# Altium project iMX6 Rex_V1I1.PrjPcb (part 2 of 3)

## Sheet [08] - CPU - SPI, I2C, SD, MMC.SchDoc
size A2; DocumentNumber: 8; SheetNumber: 8; SheetTotal: 20
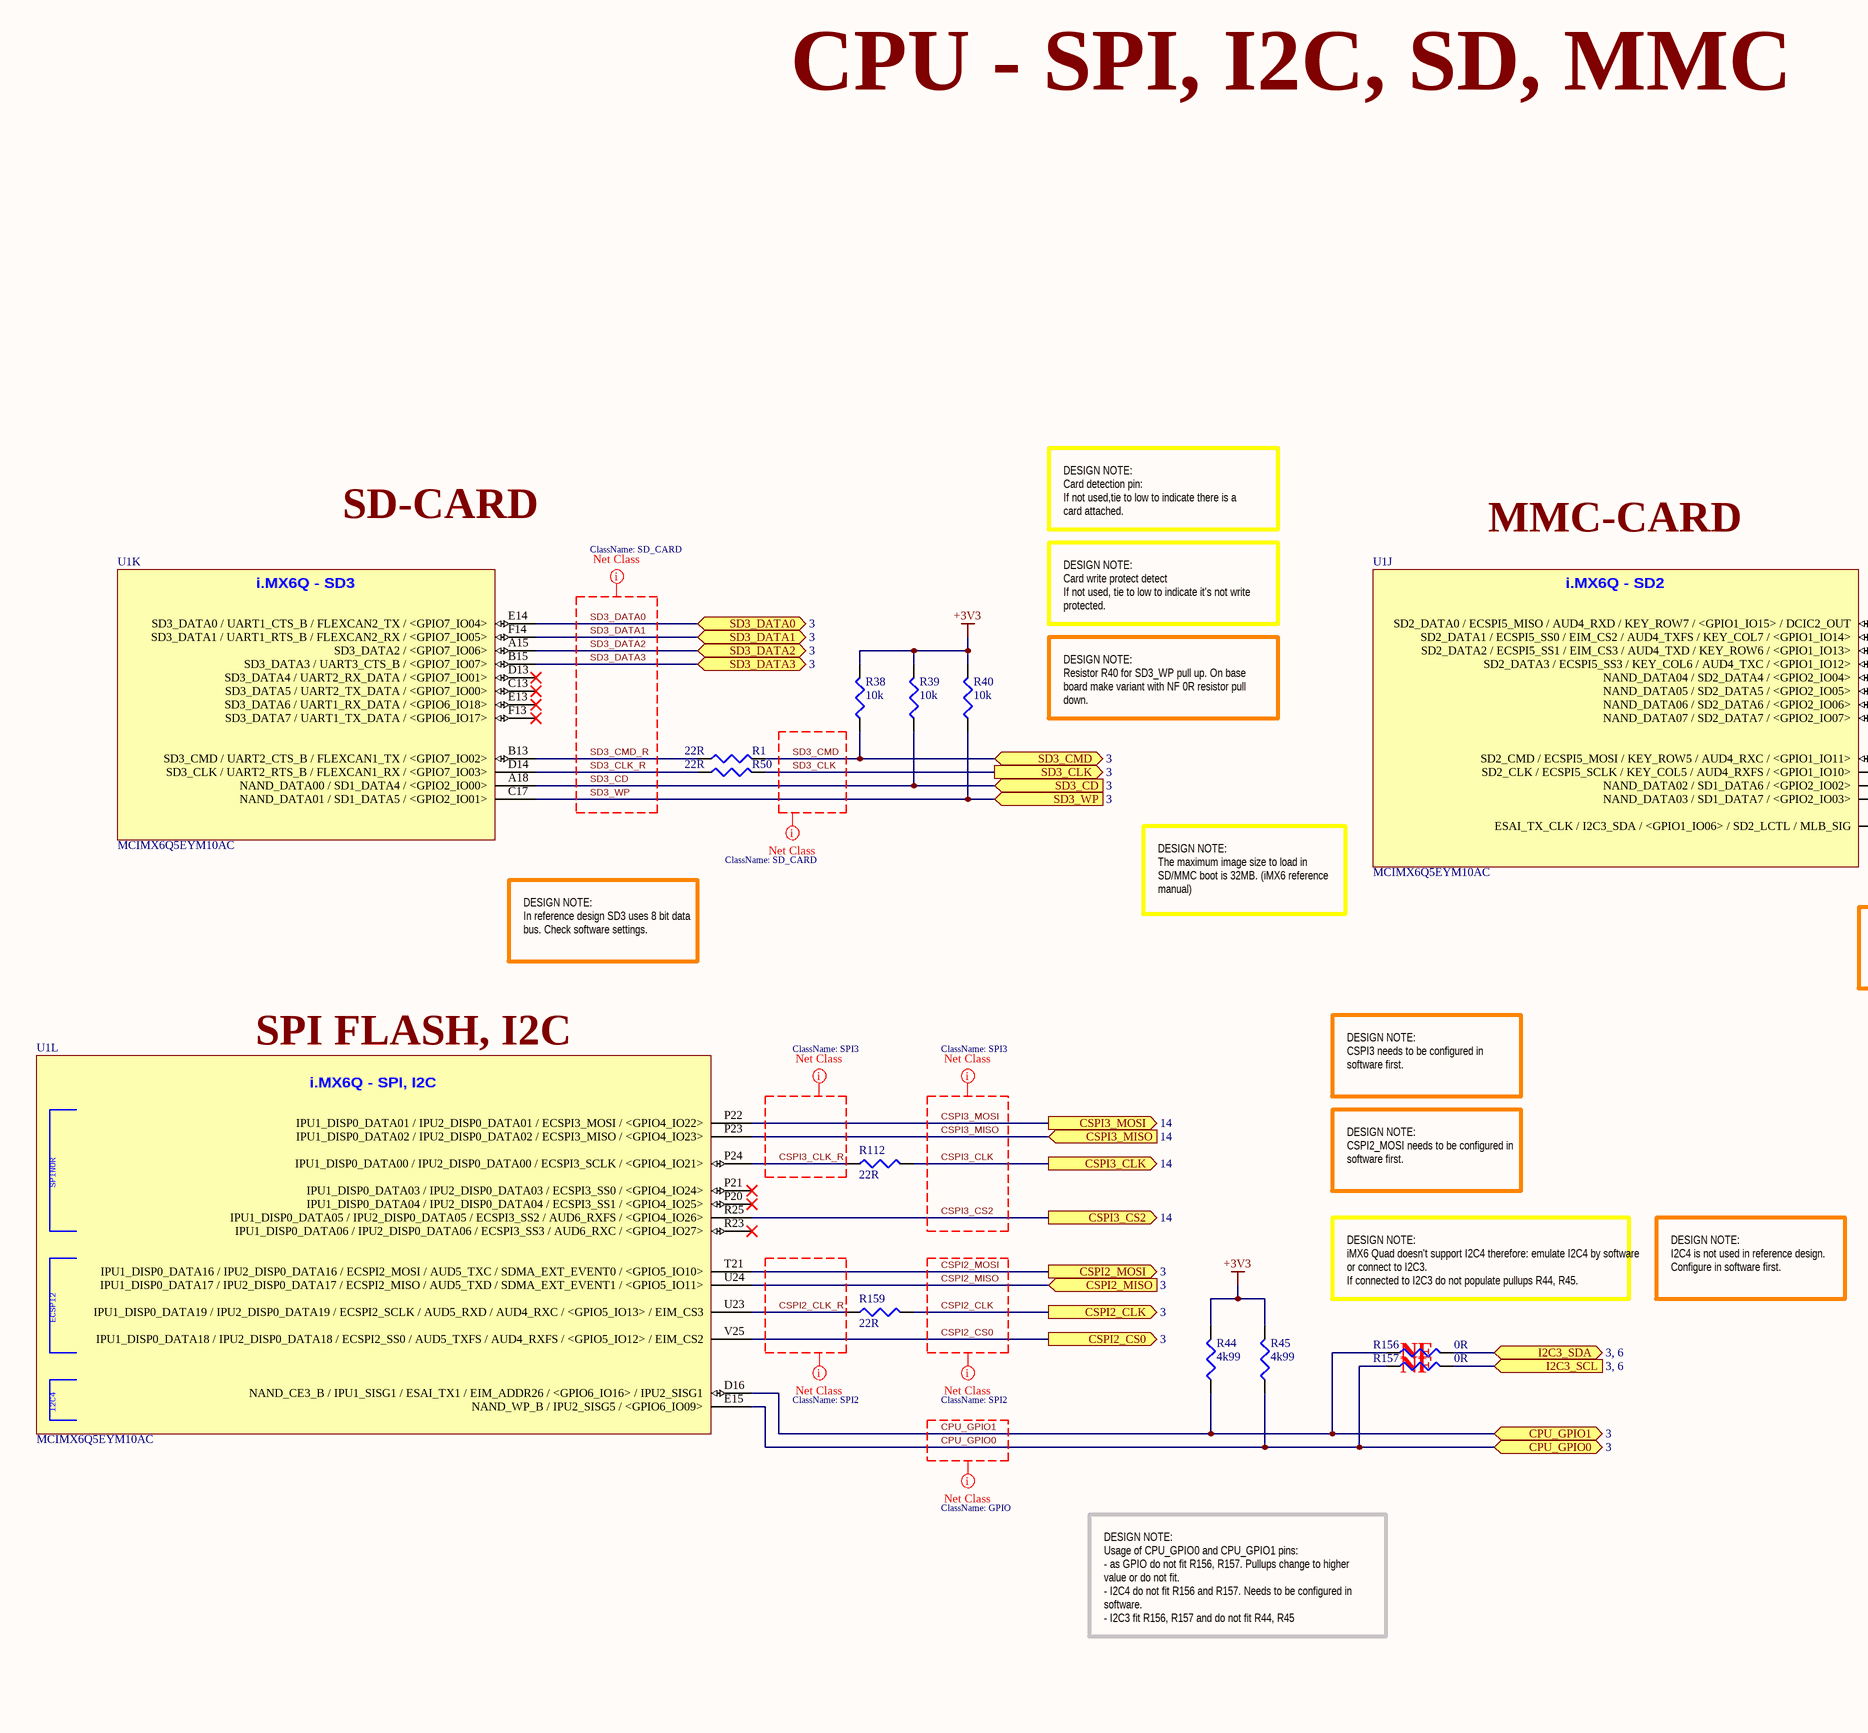
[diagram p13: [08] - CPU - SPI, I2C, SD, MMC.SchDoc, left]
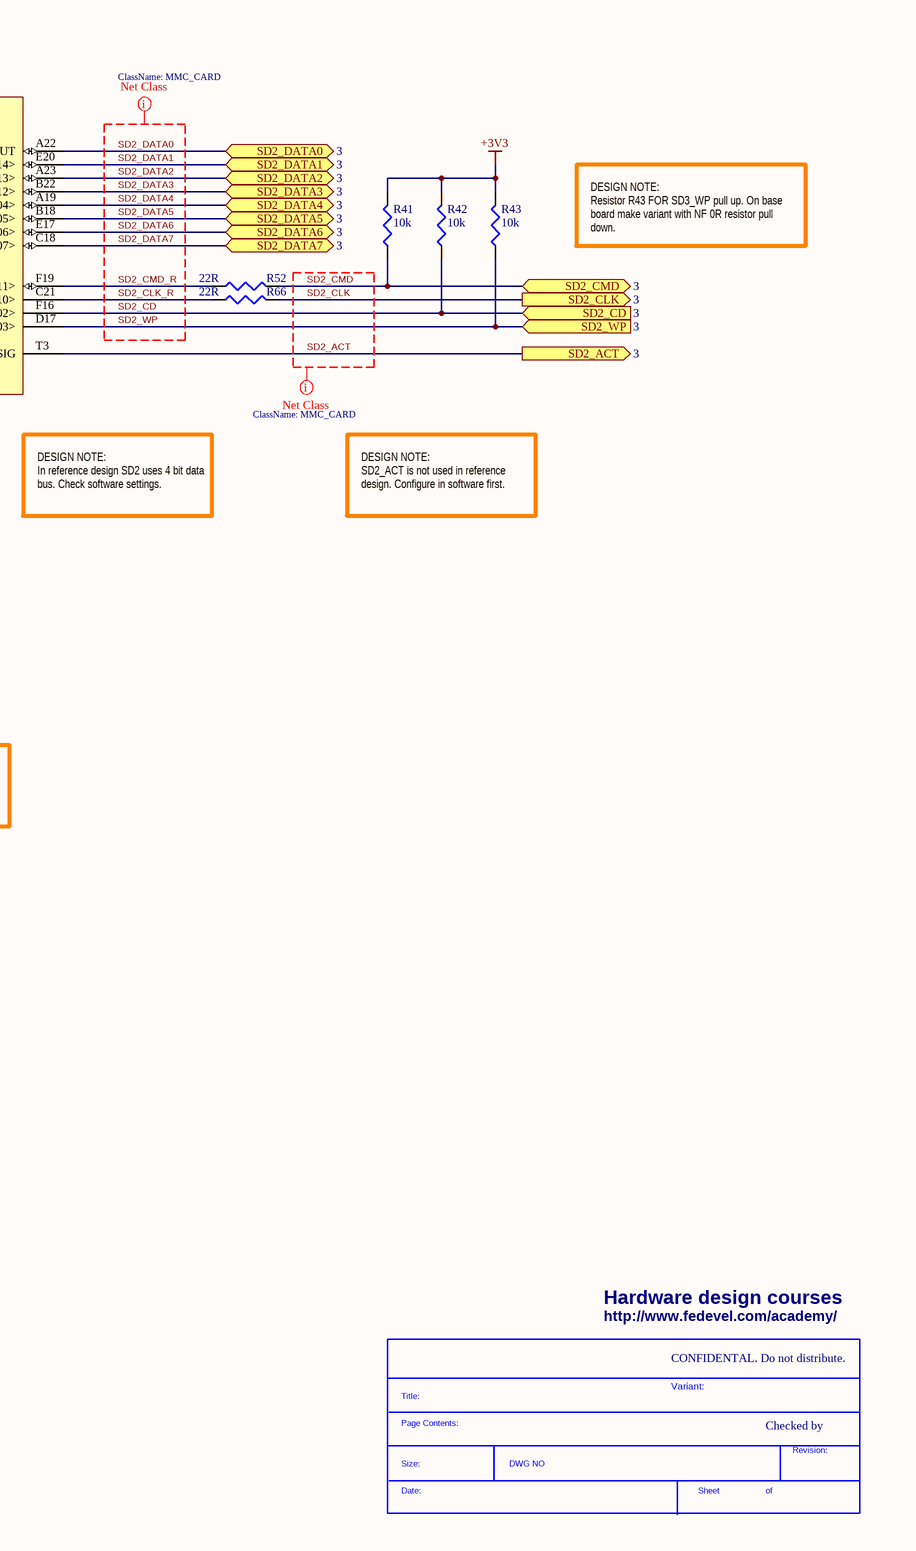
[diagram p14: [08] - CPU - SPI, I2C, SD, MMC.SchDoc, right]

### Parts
(Parts that share a designator on the sheet are numbered #1, #2 ... from top to bottom, then left to right.)
*#10  SDTitleBlock  (value not drawn)  (graphical)
R1  22R  [R0402]
R38  10k  [R0402]
R39  10k  [R0402]
R40  10k  [R0402]
R41  10k  [R0402]
R42  10k  [R0402]
R43  10k  [R0402]
R44  4k99  [R0402]
R45  4k99  [R0402]
R50  22R  [R0402]
R52  22R  [R0402]
R66  22R  [R0402]
R112  22R  [R0402]
R156  0R  [R0402]
R157  0R  [R0402]
R159  22R  [R0402]
U1  MCIMX6Q5EYM10AC  [PBGA624]  (parts J,K,L of 15)

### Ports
CPU_GPIO0 (bidir, see 3), CPU_GPIO1 (bidir, see 3), CSPI2_CLK (out, see 3), CSPI2_CS0 (out, see 3), CSPI2_MISO (in, see 3), CSPI2_MOSI (out, see 3), CSPI3_CLK (out, see 14), CSPI3_CS2 (out, see 14), CSPI3_MISO (in, see 14), CSPI3_MOSI (out, see 14), I2C3_SCL (see 3, 6), I2C3_SDA (bidir, see 3, 6), SD2_ACT (out, see 3), SD2_CD (in, see 3), SD2_CLK (out, see 3), SD2_CMD (bidir, see 3), SD2_DATA0 (bidir, see 3), SD2_DATA1 (bidir, see 3), SD2_DATA2 (bidir, see 3), SD2_DATA3 (bidir, see 3), SD2_DATA4 (bidir, see 3), SD2_DATA5 (bidir, see 3), SD2_DATA6 (bidir, see 3), SD2_DATA7 (bidir, see 3), SD2_WP (in, see 3), SD3_CD (in, see 3), SD3_CLK (out, see 3), SD3_CMD (bidir, see 3), SD3_DATA0 (bidir, see 3), SD3_DATA1 (bidir, see 3), SD3_DATA2 (bidir, see 3), SD3_DATA3 (bidir, see 3), SD3_WP (in, see 3)

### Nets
+3V3: R38.2 R39.2 R40.2 R41.2 R42.2 R43.2 R44.2 R45.2
CPU_GPIO0: R45.1 R157.1 U1.E15(NAND_WP_B_/_IPU2_SISG5_/_<GPIO6_IO09>) ; port CPU_GPIO0
CPU_GPIO1: R44.1 R156.1 U1.D16(NAND_CE3_B_/_IPU1_SISG1_/_ESAI_TX1_/_EIM_ADDR26_/_<GPIO6_IO16>_/_IPU2_SISG1) ; port CPU_GPIO1
CSPI2_CLK: R159.2 ; port CSPI2_CLK
CSPI2_CLK_R: R159.1 U1.U23(IPU1_DISP0_DATA19_/_IPU2_DISP0_DATA19_/_ECSPI2_SCLK_/_AUD5_RXD_/_AUD4_RXC_/_<GPIO5_IO13>_/_EIM_CS3)
CSPI2_CS0: U1.V25(IPU1_DISP0_DATA18_/_IPU2_DISP0_DATA18_/_ECSPI2_SS0_/_AUD5_TXFS_/_AUD4_RXFS_/_<GPIO5_IO12>_/_EIM_CS2) ; port CSPI2_CS0
CSPI2_MISO: U1.U24(IPU1_DISP0_DATA17_/_IPU2_DISP0_DATA17_/_ECSPI2_MISO_/_AUD5_TXD_/_SDMA_EXT_EVENT1_/_<GPIO5_IO11>) ; port CSPI2_MISO
CSPI2_MOSI: U1.T21(IPU1_DISP0_DATA16_/_IPU2_DISP0_DATA16_/_ECSPI2_MOSI_/_AUD5_TXC_/_SDMA_EXT_EVENT0_/_<GPIO5_IO10>) ; port CSPI2_MOSI
CSPI3_CLK: R112.2 ; port CSPI3_CLK
CSPI3_CLK_R: R112.1 U1.P24(IPU1_DISP0_DATA00_/_IPU2_DISP0_DATA00_/_ECSPI3_SCLK_/_<GPIO4_IO21>)
CSPI3_CS2: U1.R25(IPU1_DISP0_DATA05_/_IPU2_DISP0_DATA05_/_ECSPI3_SS2_/_AUD6_RXFS_/_<GPIO4_IO26>) ; port CSPI3_CS2
CSPI3_MISO: U1.P23(IPU1_DISP0_DATA02_/_IPU2_DISP0_DATA02_/_ECSPI3_MISO_/_<GPIO4_IO23>) ; port CSPI3_MISO
CSPI3_MOSI: U1.P22(IPU1_DISP0_DATA01_/_IPU2_DISP0_DATA01_/_ECSPI3_MOSI_/_<GPIO4_IO22>) ; port CSPI3_MOSI
I2C3_SCL: R157.2 ; port I2C3_SCL
I2C3_SDA: R156.2 ; port I2C3_SDA
SD2_ACT: U1.T3(ESAI_TX_CLK_/_I2C3_SDA_/_<GPIO1_IO06>_/_SD2_LCTL_/_MLB_SIG) ; port SD2_ACT
SD2_CD: R42.1 U1.F16(NAND_DATA02_/_SD1_DATA6_/_<GPIO2_IO02>) ; port SD2_CD
SD2_CLK: R66.2 ; port SD2_CLK
SD2_CLK_R: R66.1 U1.C21(SD2_CLK_/_ECSPI5_SCLK_/_KEY_COL5_/_AUD4_RXFS_/_<GPIO1_IO10>)
SD2_CMD: R41.1 R52.2 ; port SD2_CMD
SD2_CMD_R: R52.1 U1.F19(SD2_CMD_/_ECSPI5_MOSI_/_KEY_ROW5_/_AUD4_RXC_/_<GPIO1_IO11>)
SD2_DATA0: U1.A22(SD2_DATA0_/_ECSPI5_MISO_/_AUD4_RXD_/_KEY_ROW7_/_<GPIO1_IO15>_/_DCIC2_OUT) ; port SD2_DATA0
SD2_DATA1: U1.E20(SD2_DATA1_/_ECSPI5_SS0_/_EIM_CS2_/_AUD4_TXFS_/_KEY_COL7_/_<GPIO1_IO14>) ; port SD2_DATA1
SD2_DATA2: U1.A23(SD2_DATA2_/_ECSPI5_SS1_/_EIM_CS3_/_AUD4_TXD_/_KEY_ROW6_/_<GPIO1_IO13>) ; port SD2_DATA2
SD2_DATA3: U1.B22(SD2_DATA3_/_ECSPI5_SS3_/_KEY_COL6_/_AUD4_TXC_/_<GPIO1_IO12>) ; port SD2_DATA3
SD2_DATA4: U1.A19(NAND_DATA04_/_SD2_DATA4_/_<GPIO2_IO04>) ; port SD2_DATA4
SD2_DATA5: U1.B18(NAND_DATA05_/_SD2_DATA5_/_<GPIO2_IO05>) ; port SD2_DATA5
SD2_DATA6: U1.E17(NAND_DATA06_/_SD2_DATA6_/_<GPIO2_IO06>) ; port SD2_DATA6
SD2_DATA7: U1.C18(NAND_DATA07_/_SD2_DATA7_/_<GPIO2_IO07>) ; port SD2_DATA7
SD2_WP: R43.1 U1.D17(NAND_DATA03_/_SD1_DATA7_/_<GPIO2_IO03>) ; port SD2_WP
SD3_CD: R39.1 U1.A18(NAND_DATA00_/_SD1_DATA4_/_<GPIO2_IO00>) ; port SD3_CD
SD3_CLK: R50.2 ; port SD3_CLK
SD3_CLK_R: R50.1 U1.D14(SD3_CLK_/_UART2_RTS_B_/_FLEXCAN1_RX_/_<GPIO7_IO03>)
SD3_CMD: R1.2 R38.1 ; port SD3_CMD
SD3_CMD_R: R1.1 U1.B13(SD3_CMD_/_UART2_CTS_B_/_FLEXCAN1_TX_/_<GPIO7_IO02>)
SD3_DATA0: U1.E14(SD3_DATA0_/_UART1_CTS_B_/_FLEXCAN2_TX_/_<GPIO7_IO04>) ; port SD3_DATA0
SD3_DATA1: U1.F14(SD3_DATA1_/_UART1_RTS_B_/_FLEXCAN2_RX_/_<GPIO7_IO05>) ; port SD3_DATA1
SD3_DATA2: U1.A15(SD3_DATA2_/_<GPIO7_IO06>) ; port SD3_DATA2
SD3_DATA3: U1.B15(SD3_DATA3_/_UART3_CTS_B_/_<GPIO7_IO07>) ; port SD3_DATA3
SD3_WP: R40.1 U1.C17(NAND_DATA01_/_SD1_DATA5_/_<GPIO2_IO01>) ; port SD3_WP

Not connected (* = marked no-connect by the designer): U1 C13(SD3_DATA5_/_UART2_TX_DATA_/_<GPIO7_IO00>)* D13(SD3_DATA4_/_UART2_RX_DATA_/_<GPIO7_IO01>)* E13(SD3_DATA6_/_UART1_RX_DATA_/_<GPIO6_IO18>)* F13(SD3_DATA7_/_UART1_TX_DATA_/_<GPIO6_IO17>)* P20(IPU1_DISP0_DATA04_/_IPU2_DISP0_DATA04_/_ECSPI3_SS1_/_<GPIO4_IO25>)* P21(IPU1_DISP0_DATA03_/_IPU2_DISP0_DATA03_/_ECSPI3_SS0_/_<GPIO4_IO24>)* R23(IPU1_DISP0_DATA06_/_IPU2_DISP0_DATA06_/_ECSPI3_SS3_/_AUD6_RXC_/_<GPIO4_IO27>)*

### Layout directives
net class SPI3: CSPI3_CLK, CSPI3_CLK_R, CSPI3_CS2, CSPI3_MISO, CSPI3_MOSI
net class SPI2: CSPI2_CLK, CSPI2_CLK_R, CSPI2_CS0, CSPI2_MISO, CSPI2_MOSI
net class GPIO: CPU_GPIO0, CPU_GPIO1
net class SD_CARD: SD3_CD, SD3_CLK, SD3_CLK_R, SD3_CMD, SD3_CMD_R, SD3_DATA0, SD3_DATA1, SD3_DATA2, SD3_DATA3, SD3_WP
net class MMC_CARD: SD2_ACT, SD2_CD, SD2_CLK, SD2_CLK_R, SD2_CMD, SD2_CMD_R, SD2_DATA0, SD2_DATA1, SD2_DATA2, SD2_DATA3, SD2_DATA4, SD2_DATA5, SD2_DATA6, SD2_DATA7, SD2_WP

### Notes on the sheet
- CPU - SPI, I2C, SD, MMC
- SD-CARD
- DESIGN NOTE:
  Card detection pin:
  If not used,tie to low to indicate there is a card attached.
- MMC-CARD
- DESIGN NOTE:
  Card write protect detect
  If not used, tie to low to indicate it's not write protected.
- DESIGN NOTE:
  Resistor R40 for SD3_WP pull up. On base board make variant with NF 0R resistor pull down.
- DESIGN NOTE:
  Resistor R43 FOR SD3_WP pull up. On base board make variant with NF 0R resistor pull down.
- DESIGN NOTE:
  The maximum image size to load in SD/MMC boot is 32MB. (iMX6 reference manual)
- DESIGN NOTE:
  In reference design SD3 uses 8 bit data bus. Check software settings.
- DESIGN NOTE:
  In reference design SD2 uses 4 bit data bus. Check software settings.
- DESIGN NOTE:
  SD2_ACT is not used in reference design. Configure in software first.
- SPI FLASH, I2C
- DESIGN NOTE:
  CSPI3 needs to be configured in software first.
- DESIGN NOTE:
  CSPI2_MOSI needs to be configured in software first.
- DESIGN NOTE:
  iMX6 Quad doesn't support I2C4 therefore: emulate I2C4 by software or connect to I2C3.
  If connected to I2C3 do not populate pullups R44, R45.
- DESIGN NOTE:
  I2C4 is not used in reference design. Configure in software first.
- NF
- DESIGN NOTE:
  Usage of CPU_GPIO0 and CPU_GPIO1 pins:
  - as GPIO do not fit R156, R157. Pullups change to higher value or do not fit.
  - I2C4 do not fit R156 and R157. Needs to be configured in software.
  - I2C3 fit R156, R157 and do not fit R44, R45
- Hardware design courses
- http://www.fedevel.com/academy/
- CONFIDENTAL. Do not distribute.
- Variant:
- Checked by

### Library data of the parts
R1 R50 R52 R66 R112 R159 = RC0402FR-0722RL: RES 22.0 OHM 1/16W 1% 0402 SMD; Manufacturer: Yageo; Resistance (Ohms): 22; Power (Watts): 0.063W, 1/16W; .Checked PCB: used; Temperature Coefficient: ±100ppm/°C
R38-R43 = RC0402FR-0710KL: RES 10.0K OHM 1/16W 1% 0402 SMD; Manufacturer: Yageo; Power (Watts): 0.063W, 1/16W; .Checked PCB: used; Temperature Coefficient: ±100ppm/°C
R44 R45 = RMCF0402FT4K99: RES TF 4.99K OHM 1% 1/16W 0402; Manufacturer: Stackpole Electronics Inc; Power (Watts): 0.063W, 1/16W; .Checked PCB: used; Temperature Coefficient: ±100ppm/°C
R156 R157 = RC0402JR-070RL: RES 0.0 OHM 1/16W 0402 SMD; Manufacturer: Yageo; Resistance (Ohms): 0.0; Power (Watts): 0.063W, 1/16W; Tolerance: Jumper; .Checked PCB: used
U1 = MCIMX6Q5EYM10AC: IC MCU 32BIT ARM QUAD 624FCBGA; Manufacturer: Freescale Semiconductor; Core Processor: ARM® Cortex™-A9; Core Size: 32-Bit Quad-Core; Speed: 1.0GHz; Connectivity: CAN, EBI/EMI, ESAI, Ethernet, GPMI, I2C, MMC/SD, PCI, SATA, SPI, UART, USB, USB OTG; Peripherals: DMA, HDMI, I2S/SSI/AC97, MIPI CSI, MIMI DSI, MIPI HIS, PWM, WDT; Number of I /O: 224; Program Memory Type: External Program Memory; RAM Size: 256K x 8; Voltage - Supply (Vcc/Vdd): 0.925 V ~ 1.5 V; Oscillator Type: Internal; .Creator: MM; .Checked PCB: MM, checked by RF

## Sheet [03] - CONNECTORS.SchDoc
size A2; DocumentNumber: 3; SheetNumber: 3; SheetTotal: 20
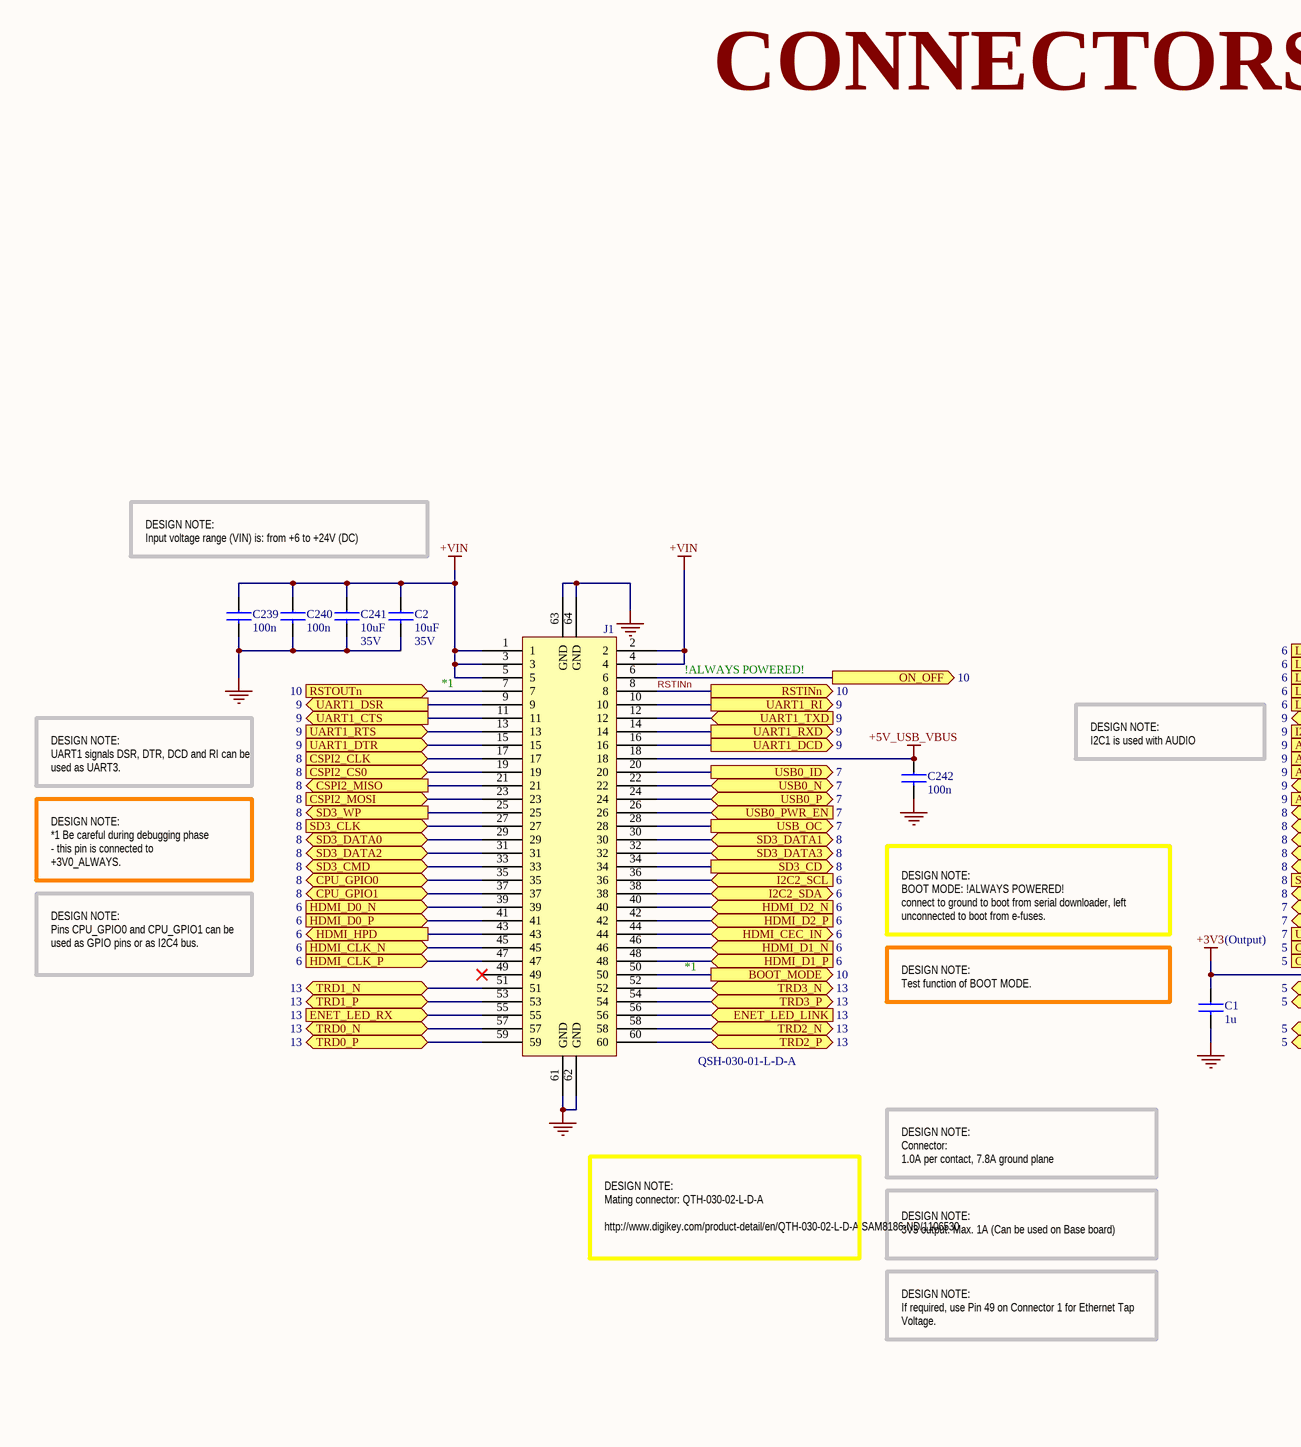
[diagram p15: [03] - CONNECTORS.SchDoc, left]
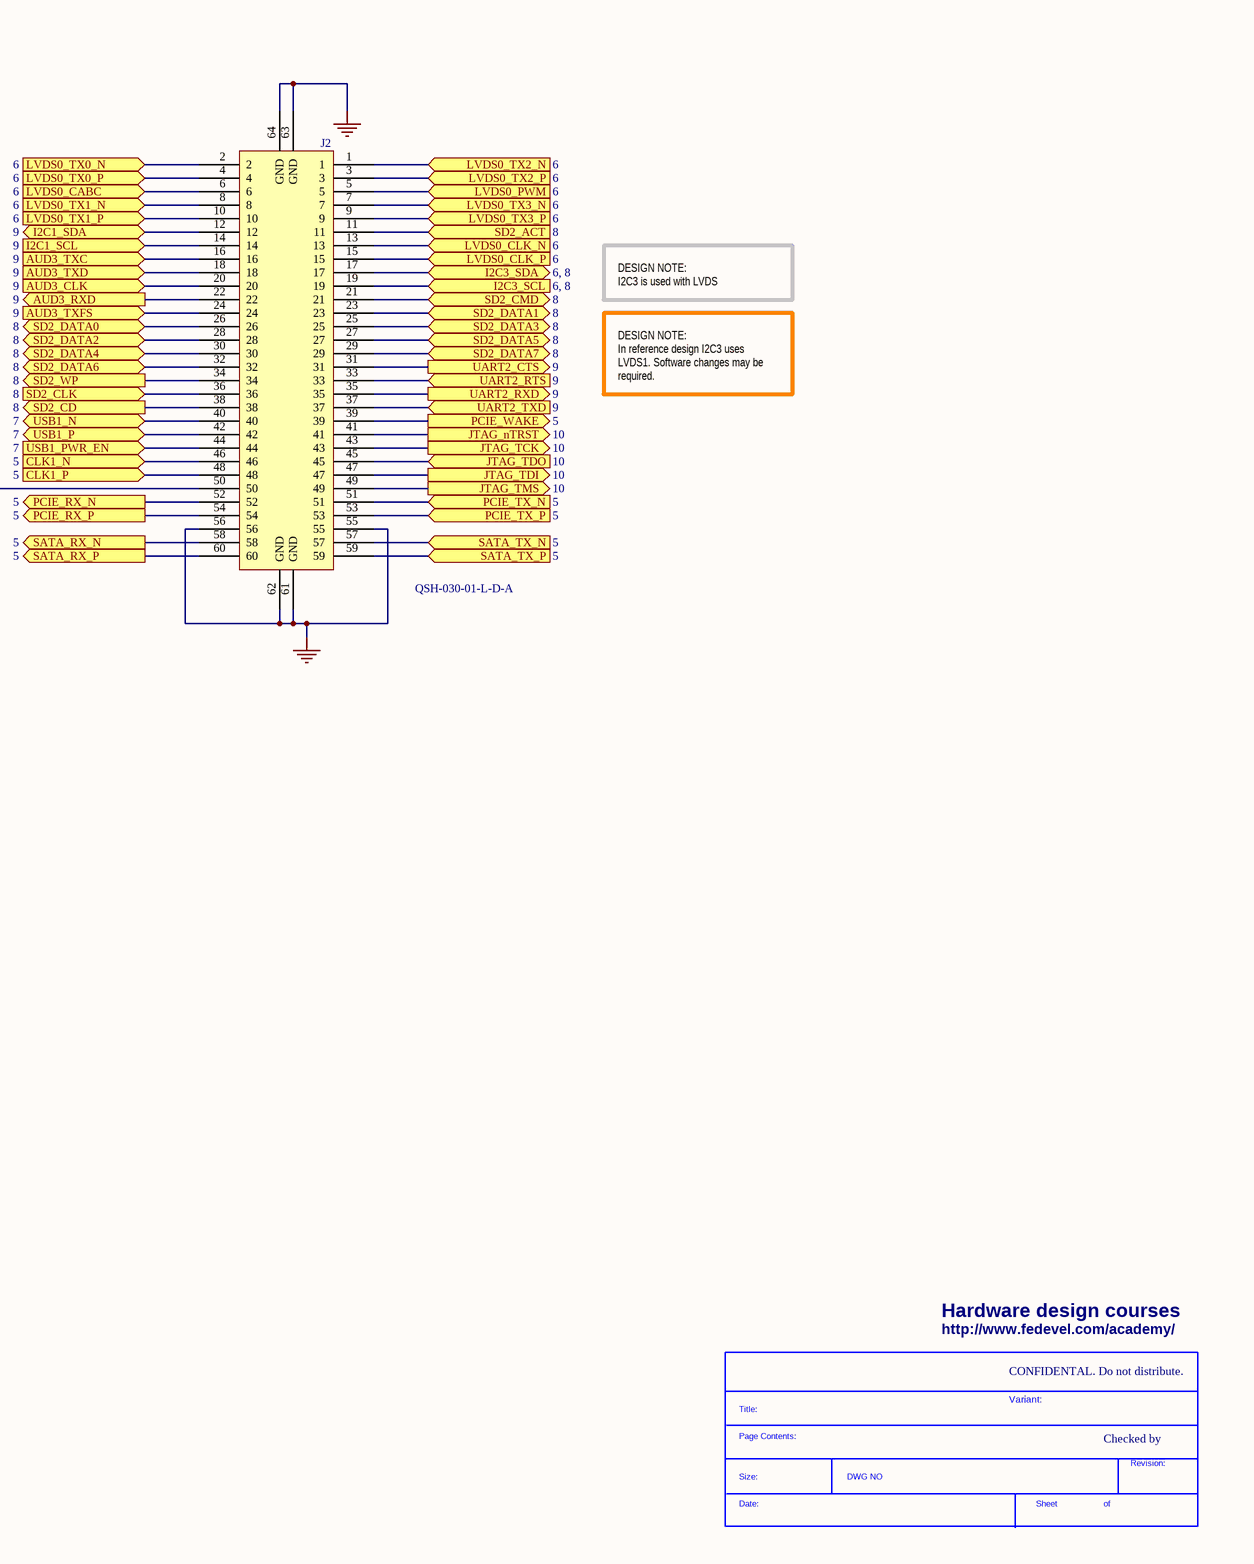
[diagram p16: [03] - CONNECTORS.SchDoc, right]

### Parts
(Parts that share a designator on the sheet are numbered #1, #2 ... from top to bottom, then left to right.)
*#11  SDTitleBlock  (value not drawn)  (graphical)
C1  1u  [C0402]
C2  10uF  Voltage - Rated: 35V  [C1206]
C239  100n  [C0402]
C240  100n  [C0402]
C241  10uF  Voltage - Rated: 35V  [C1206]
C242  100n  [C0402]
J1  QSH-030-01-L-D-A  [QSH-030-01-L-D-A]
J2  QSH-030-01-L-D-A  [QSH-030-01-L-D-A]

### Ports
AUD3_CLK (in, see 9), AUD3_RXD (out, see 9), AUD3_TXC (in, see 9), AUD3_TXD (in, see 9), AUD3_TXFS (in, see 9), BOOT_MODE (out, see 10), CLK1_N (in, see 5), CLK1_P (in, see 5), CPU_GPIO0 (bidir, see 8), CPU_GPIO1 (bidir, see 8), CSPI2_CLK (in, see 8), CSPI2_CS0 (in, see 8), CSPI2_MISO (out, see 8), CSPI2_MOSI (in, see 8), ENET_LED_LINK (in, see 13), ENET_LED_RX (in, see 13), HDMI_CEC_IN (bidir, see 6), HDMI_CLK_N (in, see 6), HDMI_CLK_P (in, see 6), HDMI_D0_N (in, see 6), HDMI_D0_P (in, see 6), HDMI_D1_N (in, see 6), HDMI_D1_P (in, see 6), HDMI_D2_N (in, see 6), HDMI_D2_P (in, see 6), HDMI_HPD (out, see 6), I2C1_SCL (in, see 9), I2C1_SDA (bidir, see 9), I2C2_SCL (in, see 6), I2C2_SDA (bidir, see 6), I2C3_SCL (see 6, 8), I2C3_SDA (bidir, see 6, 8), JTAG_nTRST (out, see 10), JTAG_TCK (out, see 10), JTAG_TDI (out, see 10), JTAG_TDO (in, see 10), JTAG_TMS (out, see 10), LVDS0_CABC (in, see 6), LVDS0_CLK_N (in, see 6), LVDS0_CLK_P (in, see 6), LVDS0_PWM (in, see 6), LVDS0_TX0_N (in, see 6), LVDS0_TX0_P (in, see 6), LVDS0_TX1_N (in, see 6), LVDS0_TX1_P (in, see 6), LVDS0_TX2_N (in, see 6), LVDS0_TX2_P (in, see 6), LVDS0_TX3_N (in, see 6), LVDS0_TX3_P (in, see 6), ON_OFF (see 10), PCIE_RX_N (out, see 5), PCIE_RX_P (out, see 5), PCIE_TX_N (in, see 5), PCIE_TX_P (in, see 5), PCIE_WAKE (out, see 5), RSTINn (out, see 10), RSTOUTn (see 10), SATA_RX_N (out, see 5), SATA_RX_P (out, see 5), SATA_TX_N (in, see 5), SATA_TX_P (in, see 5), SD2_ACT (in, see 8), SD2_CD (out, see 8), SD2_CLK (in, see 8), SD2_CMD (bidir, see 8), SD2_DATA0 (bidir, see 8), SD2_DATA1 (bidir, see 8), SD2_DATA2 (bidir, see 8), SD2_DATA3 (bidir, see 8), SD2_DATA4 (bidir, see 8), SD2_DATA5 (bidir, see 8), SD2_DATA6 (bidir, see 8), SD2_DATA7 (bidir, see 8), SD2_WP (out, see 8), SD3_CD (out, see 8), SD3_CLK (in, see 8), SD3_CMD (bidir, see 8), SD3_DATA0 (bidir, see 8), SD3_DATA1 (bidir, see 8), SD3_DATA2 (bidir, see 8), SD3_DATA3 (bidir, see 8), SD3_WP (out, see 8), TRD0_N (bidir, see 13), TRD0_P (bidir, see 13), TRD1_N (bidir, see 13), TRD1_P (bidir, see 13), TRD2_N (bidir, see 13), TRD2_P (bidir, see 13), TRD3_N (bidir, see 13), TRD3_P (bidir, see 13), UART1_CTS (out, see 9), UART1_DCD (out, see 9), UART1_DSR (out, see 9), UART1_DTR (in, see 9), UART1_RI (out, see 9), UART1_RTS (in, see 9), UART1_RXD (out, see 9), UART1_TXD (in, see 9), UART2_CTS (out, see 9), UART2_RTS (in, see 9), UART2_RXD (out, see 9), UART2_TXD (in, see 9), USB0_ID (out, see 7), USB0_N (bidir, see 7), USB0_P (bidir, see 7), USB0_PWR_EN (in, see 7), USB1_N (bidir, see 7), USB1_P (bidir, see 7), USB1_PWR_EN (in, see 7), USB_OC (out, see 7)

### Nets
+3V3: C1.1 J2.50
+5V_USB_VBUS: C242.1 J1.18
+VIN: C2.1 C239.1 C240.1 C241.1 J1.1 J1.2 J1.3 J1.4 J1.5
GND: C1.2 C2.2 C239.2 C240.2 C241.2 C242.2 J1.61(GND) J1.62(GND) J1.63(GND) J1.64(GND) J2.55 J2.56 J2.61(GND) J2.62(GND) J2.63(GND) J2.64(GND)
AUD3_CLK: J2.20 ; port AUD3_CLK
AUD3_RXD: J2.22 ; port AUD3_RXD
AUD3_TXC: J2.16 ; port AUD3_TXC
AUD3_TXD: J2.18 ; port AUD3_TXD
AUD3_TXFS: J2.24 ; port AUD3_TXFS
BOOT_MODE: J1.50 ; port BOOT_MODE
CLK1_N: J2.46 ; port CLK1_N
CLK1_P: J2.48 ; port CLK1_P
CPU_GPIO0: J1.35 ; port CPU_GPIO0
CPU_GPIO1: J1.37 ; port CPU_GPIO1
CSPI2_CLK: J1.17 ; port CSPI2_CLK
CSPI2_CS0: J1.19 ; port CSPI2_CS0
CSPI2_MISO: J1.21 ; port CSPI2_MISO
CSPI2_MOSI: J1.23 ; port CSPI2_MOSI
ENET_LED_LINK: J1.56 ; port ENET_LED_LINK
ENET_LED_RX: J1.55 ; port ENET_LED_RX
HDMI_CEC_IN: J1.44 ; port HDMI_CEC_IN
HDMI_CLK_N: J1.45 ; port HDMI_CLK_N
HDMI_CLK_P: J1.47 ; port HDMI_CLK_P
HDMI_D0_N: J1.39 ; port HDMI_D0_N
HDMI_D0_P: J1.41 ; port HDMI_D0_P
HDMI_D1_N: J1.46 ; port HDMI_D1_N
HDMI_D1_P: J1.48 ; port HDMI_D1_P
HDMI_D2_N: J1.40 ; port HDMI_D2_N
HDMI_D2_P: J1.42 ; port HDMI_D2_P
HDMI_HPD: J1.43 ; port HDMI_HPD
I2C1_SCL: J2.14 ; port I2C1_SCL
I2C1_SDA: J2.12 ; port I2C1_SDA
I2C2_SCL: J1.36 ; port I2C2_SCL
I2C2_SDA: J1.38 ; port I2C2_SDA
I2C3_SCL: J2.19 ; port I2C3_SCL
I2C3_SDA: J2.17 ; port I2C3_SDA
JTAG_nTRST: J2.41 ; port JTAG_nTRST
JTAG_TCK: J2.43 ; port JTAG_TCK
JTAG_TDI: J2.47 ; port JTAG_TDI
JTAG_TDO: J2.45 ; port JTAG_TDO
JTAG_TMS: J2.49 ; port JTAG_TMS
LVDS0_CABC: J2.6 ; port LVDS0_CABC
LVDS0_CLK_N: J2.13 ; port LVDS0_CLK_N
LVDS0_CLK_P: J2.15 ; port LVDS0_CLK_P
LVDS0_PWM: J2.5 ; port LVDS0_PWM
LVDS0_TX0_N: J2.2 ; port LVDS0_TX0_N
LVDS0_TX0_P: J2.4 ; port LVDS0_TX0_P
LVDS0_TX1_N: J2.8 ; port LVDS0_TX1_N
LVDS0_TX1_P: J2.10 ; port LVDS0_TX1_P
LVDS0_TX2_N: J2.1 ; port LVDS0_TX2_N
LVDS0_TX2_P: J2.3 ; port LVDS0_TX2_P
LVDS0_TX3_N: J2.7 ; port LVDS0_TX3_N
LVDS0_TX3_P: J2.9 ; port LVDS0_TX3_P
ON_OFF: J1.6 ; port ON_OFF
PCIE_RX_N: J2.52 ; port PCIE_RX_N
PCIE_RX_P: J2.54 ; port PCIE_RX_P
PCIE_TX_N: J2.51 ; port PCIE_TX_N
PCIE_TX_P: J2.53 ; port PCIE_TX_P
PCIE_WAKE: J2.39 ; port PCIE_WAKE
RSTINn: J1.8 ; port RSTINn
RSTOUTn: J1.7 ; port RSTOUTn
SATA_RX_N: J2.58 ; port SATA_RX_N
SATA_RX_P: J2.60 ; port SATA_RX_P
SATA_TX_N: J2.57 ; port SATA_TX_N
SATA_TX_P: J2.59 ; port SATA_TX_P
SD2_ACT: J2.11 ; port SD2_ACT
SD2_CD: J2.38 ; port SD2_CD
SD2_CLK: J2.36 ; port SD2_CLK
SD2_CMD: J2.21 ; port SD2_CMD
SD2_DATA0: J2.26 ; port SD2_DATA0
SD2_DATA1: J2.23 ; port SD2_DATA1
SD2_DATA2: J2.28 ; port SD2_DATA2
SD2_DATA3: J2.25 ; port SD2_DATA3
SD2_DATA4: J2.30 ; port SD2_DATA4
SD2_DATA5: J2.27 ; port SD2_DATA5
SD2_DATA6: J2.32 ; port SD2_DATA6
SD2_DATA7: J2.29 ; port SD2_DATA7
SD2_WP: J2.34 ; port SD2_WP
SD3_CD: J1.34 ; port SD3_CD
SD3_CLK: J1.27 ; port SD3_CLK
SD3_CMD: J1.33 ; port SD3_CMD
SD3_DATA0: J1.29 ; port SD3_DATA0
SD3_DATA1: J1.30 ; port SD3_DATA1
SD3_DATA2: J1.31 ; port SD3_DATA2
SD3_DATA3: J1.32 ; port SD3_DATA3
SD3_WP: J1.25 ; port SD3_WP
TRD0_N: J1.57 ; port TRD0_N
TRD0_P: J1.59 ; port TRD0_P
TRD1_N: J1.51 ; port TRD1_N
TRD1_P: J1.53 ; port TRD1_P
TRD2_N: J1.58 ; port TRD2_N
TRD2_P: J1.60 ; port TRD2_P
TRD3_N: J1.52 ; port TRD3_N
TRD3_P: J1.54 ; port TRD3_P
UART1_CTS: J1.11 ; port UART1_CTS
UART1_DCD: J1.16 ; port UART1_DCD
UART1_DSR: J1.9 ; port UART1_DSR
UART1_DTR: J1.15 ; port UART1_DTR
UART1_RI: J1.10 ; port UART1_RI
UART1_RTS: J1.13 ; port UART1_RTS
UART1_RXD: J1.14 ; port UART1_RXD
UART1_TXD: J1.12 ; port UART1_TXD
UART2_CTS: J2.31 ; port UART2_CTS
UART2_RTS: J2.33 ; port UART2_RTS
UART2_RXD: J2.35 ; port UART2_RXD
UART2_TXD: J2.37 ; port UART2_TXD
USB0_ID: J1.20 ; port USB0_ID
USB0_N: J1.22 ; port USB0_N
USB0_P: J1.24 ; port USB0_P
USB0_PWR_EN: J1.26 ; port USB0_PWR_EN
USB1_N: J2.40 ; port USB1_N
USB1_P: J2.42 ; port USB1_P
USB1_PWR_EN: J2.44 ; port USB1_PWR_EN
USB_OC: J1.28 ; port USB_OC

Not connected (* = marked no-connect by the designer): J1 49* 65(HOLE1) 66(HOLE2); J2 65(HOLE1) 66(HOLE2)

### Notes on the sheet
- CONNECTORS
- DESIGN NOTE:
  Input voltage range (VIN) is: from +6 to +24V (DC)
- *1
- !ALWAYS POWERED!
- DESIGN NOTE:
  UART1 signals DSR, DTR, DCD and RI can be used as UART3.
- DESIGN NOTE:
  I2C1 is used with AUDIO
- DESIGN NOTE:
  I2C3 is used with LVDS
- DESIGN NOTE:
  *1 Be careful during debugging phase - this pin is connected to +3V0_ALWAYS.
- DESIGN NOTE:
  In reference design I2C3 uses LVDS1. Software changes may be required.
- DESIGN NOTE:
  BOOT MODE: !ALWAYS POWERED!
  connect to ground to boot from serial downloader, left unconnected to boot from e-fuses.
- DESIGN NOTE:
  Pins CPU_GPIO0 and CPU_GPIO1 can be used as GPIO pins or as I2C4 bus.
- (Output)
- DESIGN NOTE:
  Test function of BOOT MODE.
- DESIGN NOTE:
  Connector:
  1.0A per contact, 7.8A ground plane
- DESIGN NOTE:
  Mating connector: QTH-030-02-L-D-A
  http://www.digikey.com/product-detail/en/QTH-030-02-L-D-A/SAM8186-ND/1106530
- DESIGN NOTE:
  3V3 output. Max. 1A (Can be used on Base board)
- DESIGN NOTE:
  If required, use Pin 49 on Connector 1 for Ethernet Tap Voltage.
- Hardware design courses
- http://www.fedevel.com/academy/
- CONFIDENTAL. Do not distribute.
- Variant:
- Checked by

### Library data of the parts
C1 = C1005X5R1C105K: CAP CER 1.0UF 16V X5R 0402; Manufacturer: TDK Corporation; Capacitance: 1.0µF; Value: 1uF; .Checked PCB: used; Description: CAP CER 1UF 16V 10% X5R 0402; Tolerance: ±10%
C2 C241 = GRM31CR6YA106KA12L: CAP CER 10UF 35V X5R 1206; Manufacturer: Murata Electronics North America; Capacitance: 10µF; .Checked PCB: used; Description: CAP CER 10UF 35V 10% X5R 1206; Tolerance: ±10%
C239 C240 C242 = C1005X5R1H104K: CAP CER .10UF 50V X5R 10% 0402; Manufacturer: TDK Corporation; Capacitance: 0.1µF; Value: 100nF; .Checked PCB: used; Description: CAP CER 0.1UF 50V 10% X5R 0402
J1 J2 = QSH-030-01-L-D-A: CONN RCPT HI-SPD .5MM 60POS DL; Manufacturer: Samtec Inc; .Checked PCB: used; Connector Type: Receptacle, Center Strip Contacts; Number of Positions: 60; Pitch: 0.020" (0.50mm); Mating connector: QTH-030-02-L-D-A; Mated Stacking Heights: 5mm, 8mm, 11mm, 16mm, 19mm, 25mm

## Sheet [10] - CPU - JTAG, CONTROL.SchDoc
size A2; DocumentNumber: 10; SheetNumber: 10; SheetTotal: 20
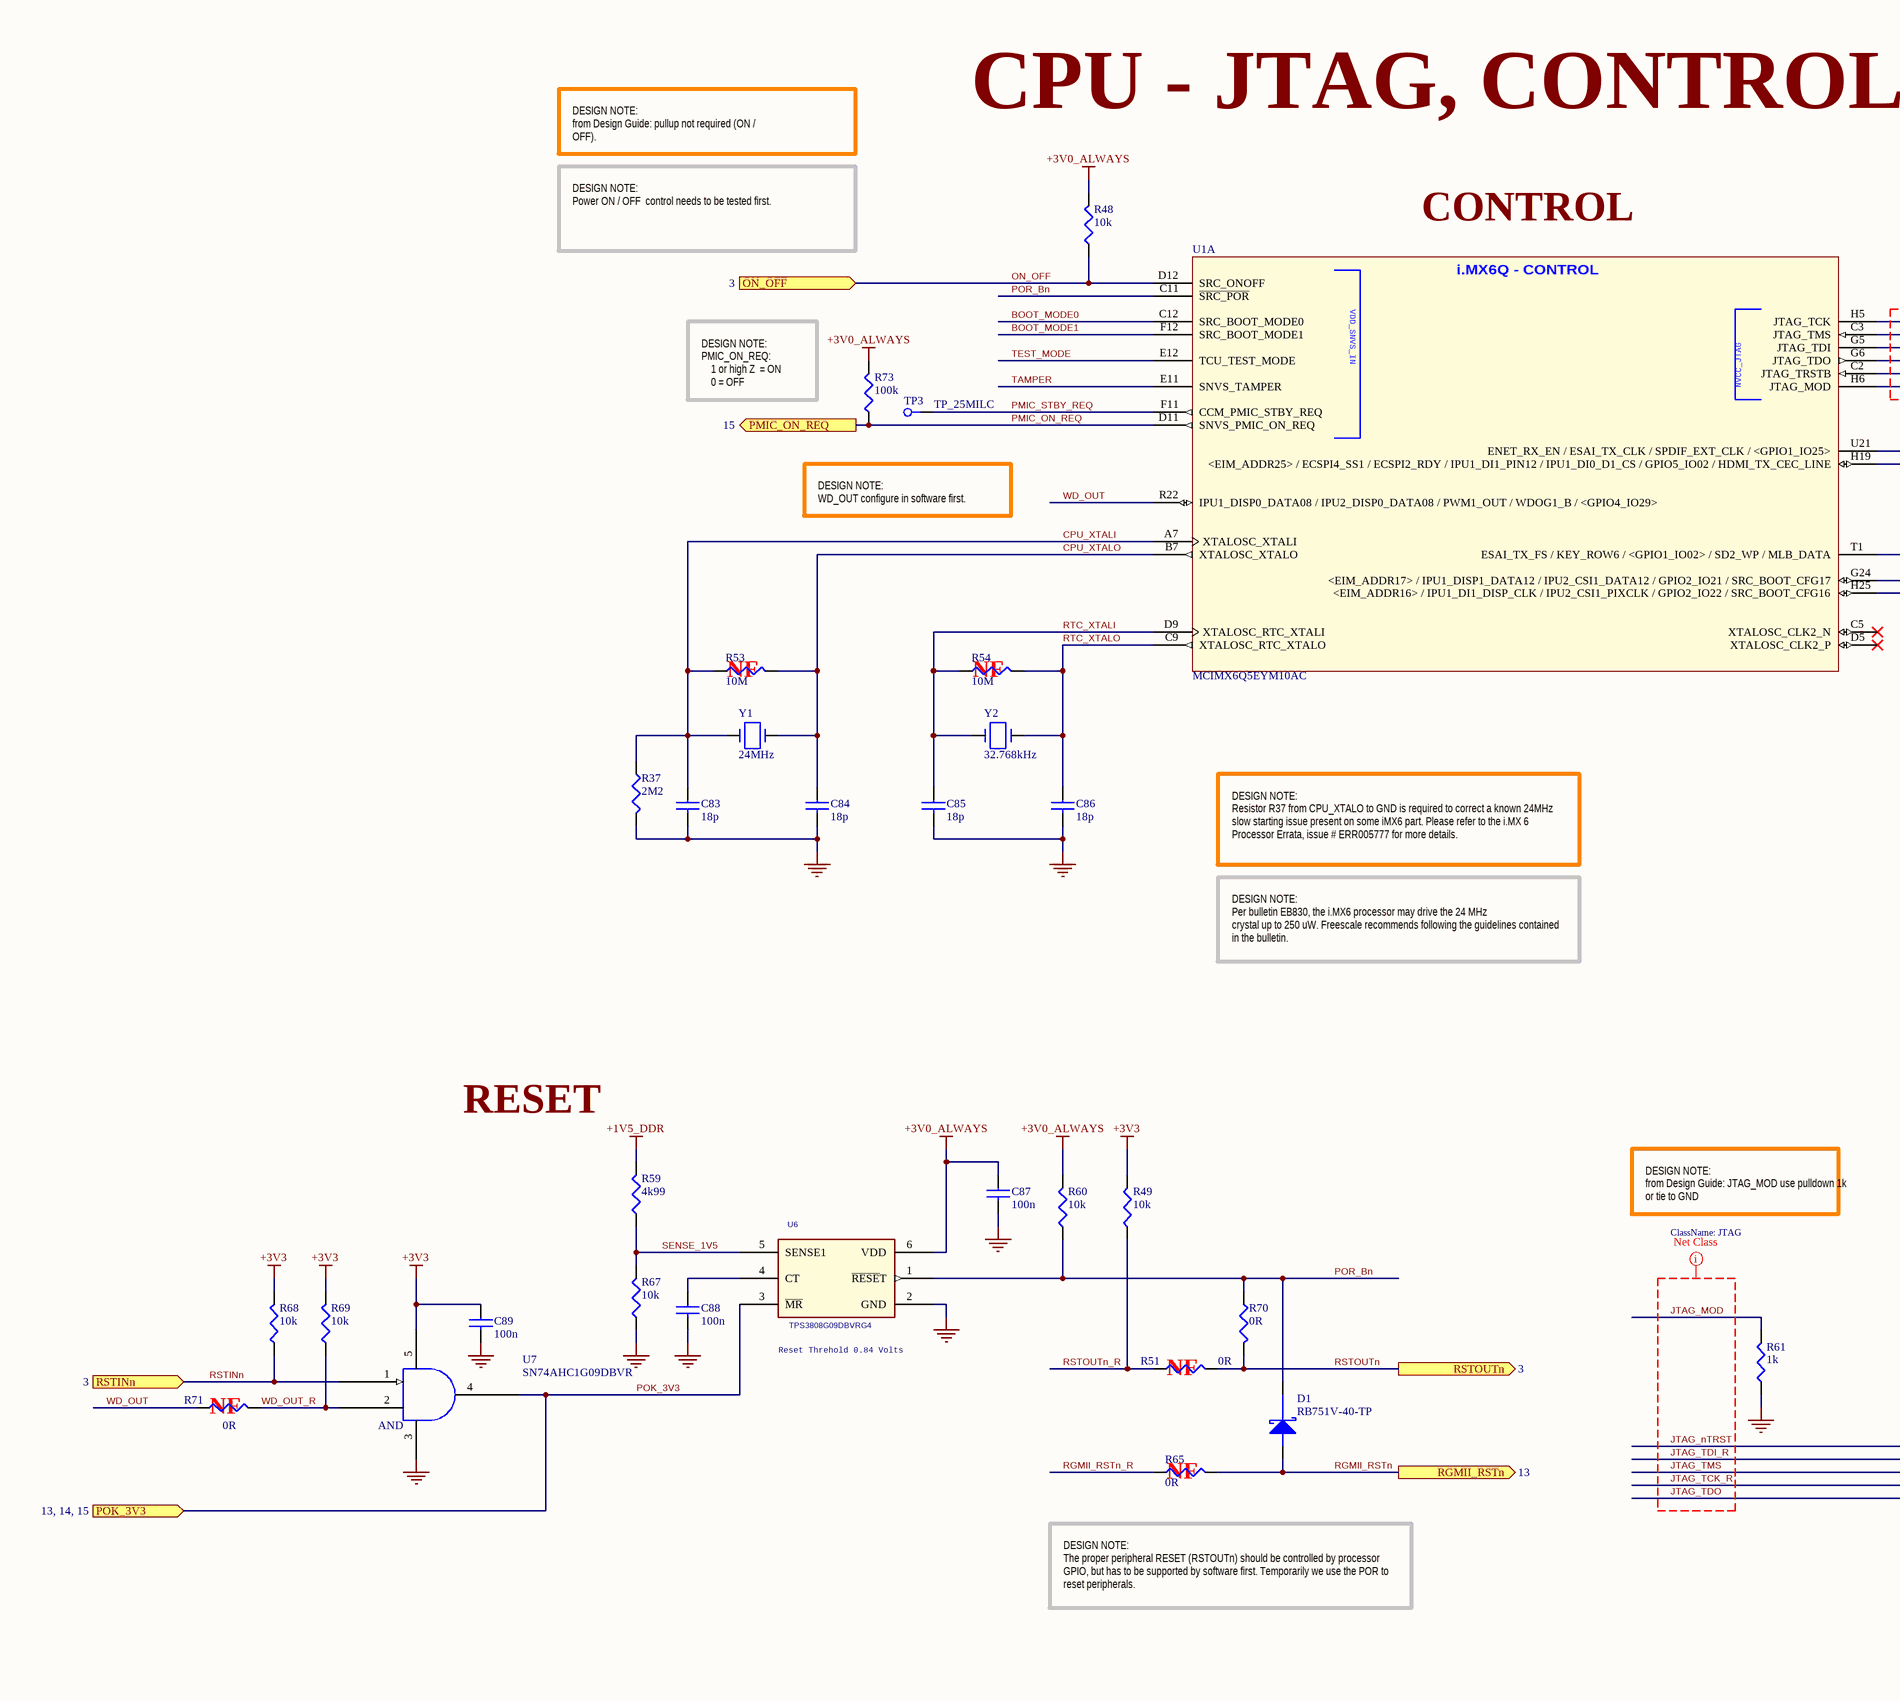
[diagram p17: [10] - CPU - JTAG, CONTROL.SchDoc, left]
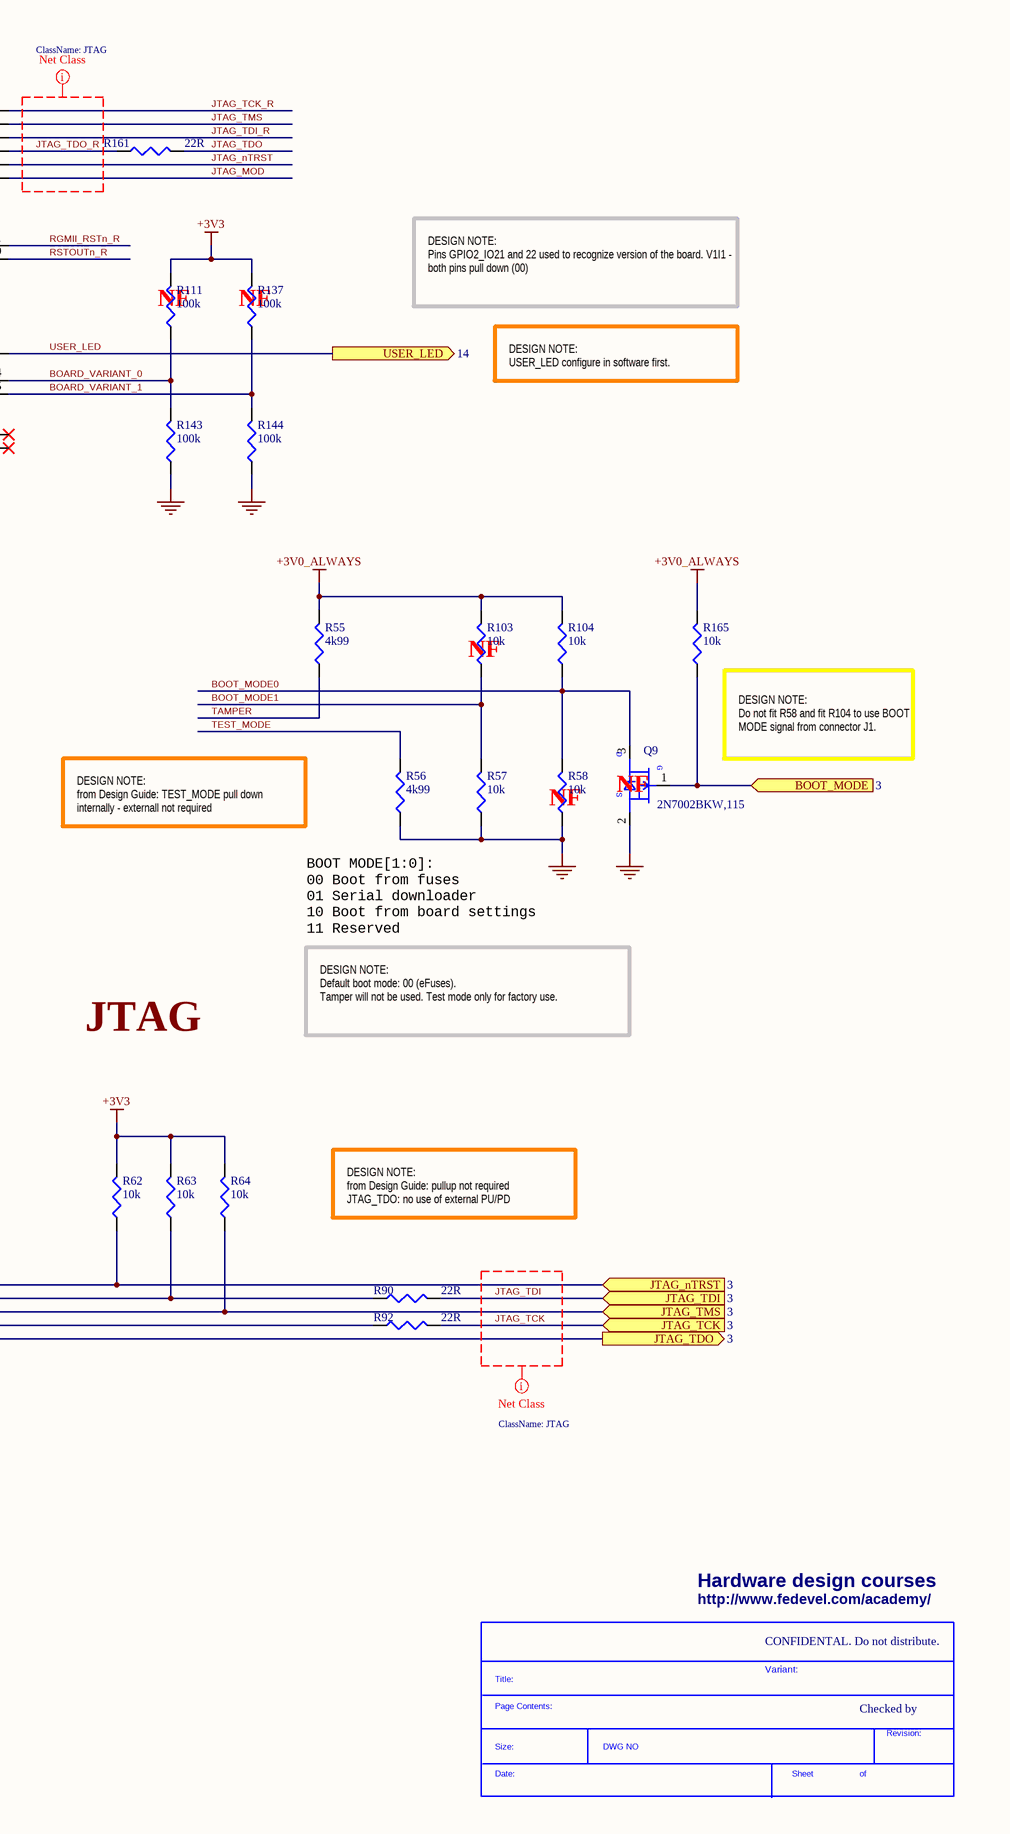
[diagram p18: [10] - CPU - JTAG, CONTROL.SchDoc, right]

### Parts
(Parts that share a designator on the sheet are numbered #1, #2 ... from top to bottom, then left to right.)
*#12  SDTitleBlock  (value not drawn)  (graphical)
C83  18p  [C0402]
C84  18p  [C0402]
C85  18p  [C0402]
C86  18p  [C0402]
C87  100n  [C0402]
C88  100n  [C0402]
C89  100n  [C0402]
D1  RB751V-40-TP  [SOD323]
Q9  2N7002BKW,115  [SC70_SOT323]
R37  2M2  [R0402]
R48  10k  [R0402]
R49  10k  [R0402]
R51  0R  [R0402]
R53  10M  [R0402]
R54  10M  [R0402]
R55  4k99  [R0402]
R56  4k99  [R0402]
R57  10k  [R0402]
R58  10k  [R0402]
R59  4k99  [R0402]
R60  10k  [R0402]
R61  1k  [R0402]
R62  10k  [R0402]
R63  10k  [R0402]
R64  10k  [R0402]
R65  0R  [R0402]
R67  10k  [R0402]
R68  10k  [R0402]
R69  10k  [R0402]
R70  0R  [R0402]
R71  0R  [R0402]
R73  100k  [R0402]
R90  22R  [R0402]
R92  22R  [R0402]
R103  10k  [R0402]
R104  10k  [R0402]
R111  100k  [R0402]
R137  100k  [R0402]
R143  100k  [R0402]
R144  100k  [R0402]
R161  22R  [R0402]
R165  10k  [R0402]
TP3  TP_25MILC  [TP_25C]  (no BOM)
U1  MCIMX6Q5EYM10AC  [PBGA624]  (part A of 15)
U6  TPS3808G09DBVRG4  [DBV_SOT_23_6]
U7  SN74AHC1G09DBVR  [DBV_SOT_23_5]
Y1  24MHz  [ABM7_v1_1]
Y2  32.768kHz  [ABS06]

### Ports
BOOT_MODE (in, see 3), JTAG_nTRST (in, see 3), JTAG_TCK (in, see 3), JTAG_TDI (in, see 3), JTAG_TDO (out, see 3), JTAG_TMS (in, see 3), ON_OFF (see 3), PMIC_ON_REQ (out, see 15), POK_3V3 (see 13, 14, 15), RGMII_RSTn (out, see 13), RSTINn (in, see 3), RSTOUTn (see 3), USER_LED (out, see 14)

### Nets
+1V5_DDR: R59.2
+3V0_ALWAYS: C87.1 R48.2 R55.2 R60.2 R73.2 R103.2 R104.2 R165.2 U6.6(VDD)
+3V3: C89.1 R49.2 R62.2 R63.2 R64.2 R68.2 R69.2 R111.2 R137.2 U7.5(VCC)
GND: C83.2 C84.2 C85.2 C86.2 C87.2 C88.2 C89.2 Q9.2(SOURCE) R37.2 R56.1 R57.1 R58.1 R61.1 R67.1 R143.1 R144.1 U6.2(GND) U7.3(GND)
BOARD_VARIANT_0: R111.1 R143.2 U1.G24(<EIM_ADDR17>_/_IPU1_DISP1_DATA12_/_IPU2_CSI1_DATA12_/_GPIO2_IO21_/_SRC_BOOT_CFG17)
BOARD_VARIANT_1: R137.1 R144.2 U1.H25(<EIM_ADDR16>_/_IPU1_DI1_DISP_CLK_/_IPU2_CSI1_PIXCLK_/_GPIO2_IO22_/_SRC_BOOT_CFG16)
BOOT_MODE: Q9.1(GATE) R165.1 ; port BOOT_MODE
BOOT_MODE0: Q9.3(DRAIN) R58.2 R104.1 U1.C12(SRC_BOOT_MODE0)
BOOT_MODE1: R57.2 R103.1 U1.F12(SRC_BOOT_MODE1)
CPU_XTALI: C83.1 R37.1 R53.1 U1.A7(XTALOSC_XTALI) Y1.1
CPU_XTALO: C84.1 R53.2 U1.B7(XTALOSC_XTALO) Y1.2
JTAG_MOD: R61.2 U1.H6(JTAG_MOD)
JTAG_nTRST: R62.1 U1.C2(JTAG_TRSTB) ; port JTAG_nTRST
JTAG_TCK: R92.2 ; port JTAG_TCK
JTAG_TCK_R: R92.1 U1.H5(JTAG_TCK)
JTAG_TDI: R90.2 ; port JTAG_TDI
JTAG_TDI_R: R63.1 R90.1 U1.G5(JTAG_TDI)
JTAG_TDO: R161.2 ; port JTAG_TDO
JTAG_TDO_R: R161.1 U1.G6(JTAG_TDO)
JTAG_TMS: R64.1 U1.C3(JTAG_TMS) ; port JTAG_TMS
ON_OFF: R48.1 U1.D12(SRC_ONOFF) ; port ON_OFF
PMIC_ON_REQ: R73.1 U1.D11(SNVS_PMIC_ON_REQ) ; port PMIC_ON_REQ
PMIC_STBY_REQ: TP3.1 U1.F11(CCM_PMIC_STBY_REQ)
POK_3V3: U6.3(~{MR}) U7.4(Y) ; port POK_3V3
POR_Bn: D1.1(cathode) R60.1 R70.1 U1.C11(~{SRC_POR}) U6.1(~{RESE}T)
RGMII_RSTn: D1.2(ANODE) R65.2 ; port RGMII_RSTn
RGMII_RSTn_R: R65.1 U1.U21(ENET_RX_EN_/_ESAI_TX_CLK_/_SPDIF_EXT_CLK_/_<GPIO1_IO25>)
RSTINn: R68.1 U7.1(A) ; port RSTINn
RSTOUTn: R51.2 R70.2 ; port RSTOUTn
RSTOUTn_R: R49.1 R51.1 U1.H19(<EIM_ADDR25>_/_ECSPI4_SS1_/_ECSPI2_RDY_/_IPU1_DI1_PIN12_/_IPU1_DI0_D1_CS_/_GPIO5_IO02_/_HDMI_TX_CEC_LINE)
RTC_XTALI: C85.1 R54.1 U1.D9(XTALOSC_RTC_XTALI) Y2.1
RTC_XTALO: C86.1 R54.2 U1.C9(XTALOSC_RTC_XTALO) Y2.2
SENSE_1V5: R59.1 R67.2 U6.5(SENSE1)
TAMPER: R55.1 U1.E11(SNVS_TAMPER)
TEST_MODE: R56.2 U1.E12(TCU_TEST_MODE)
USER_LED: U1.T1(ESAI_TX_FS_/_KEY_ROW6_/_<GPIO1_IO02>_/_SD2_WP_/_MLB_DATA) ; port USER_LED
WD_OUT: R71.1 U1.R22(IPU1_DISP0_DATA08_/_IPU2_DISP0_DATA08_/_PWM1_OUT_/_WDOG1_B_/_<GPIO4_IO29>)
WD_OUT_R: R69.1 R71.2 U7.2(B)
NetC88_1: C88.1 U6.4(CT)

Not connected (* = marked no-connect by the designer): U1 C5(XTALOSC_CLK2_N)* D5(XTALOSC_CLK2_P)*

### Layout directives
net class JTAG: JTAG_MOD, JTAG_nTRST, JTAG_TCK, JTAG_TCK_R, JTAG_TDI, JTAG_TDI_R, JTAG_TDO, JTAG_TDO_R, JTAG_TMS

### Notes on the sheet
- CPU - JTAG, CONTROL
- DESIGN NOTE:
  from Design Guide: pullup not required (ON / OFF).
- DESIGN NOTE:
  Power ON / OFF  control needs to be tested first.
- CONTROL
- DESIGN NOTE:
  PMIC_ON_REQ:
  1 or high Z  = ON
  0 = OFF
- DESIGN NOTE:
  WD_OUT configure in software first.
- (near R111) NF
- (near R137) NF
- DESIGN NOTE:
  Pins GPIO2_IO21 and 22 used to recognize version of the board. V1I1 - both pins pull down (00)
- DESIGN NOTE:
  USER_LED configure in software first.
- (near R53) NF
- (near R54) NF
- DESIGN NOTE:
  Resistor R37 from CPU_XTALO to GND is required to correct a known 24MHz slow starting issue present on some iMX6 part. Please refer to the i.MX 6 Processor Errata, issue # ERR005777 for more details.
- (near R103) NF
- DESIGN NOTE:
  Per bulletin EB830, the i.MX6 processor may drive the 24 MHz
  crystal up to 250 uW. Freescale recommends following the guidelines contained in the bulletin.
- (near R165) DESIGN NOTE:
  Do not fit R58 and fit R104 to use BOOT MODE signal from connector J1.
- DESIGN NOTE:
  from Design Guide: TEST_MODE pull down internally - externall not required
- (near R58) NF
- (near Q9) NF
- RESET
- BOOT MODE[1:0]:
  00 Boot from fuses
  01 Serial downloader
  10 Boot from board settings
  11 Reserved
- DESIGN NOTE:
  from Design Guide: JTAG_MOD use pulldown 1k or tie to GND
- JTAG
- DESIGN NOTE:
  Default boot mode: 00 (eFuses).
  Tamper will not be used. Test mode only for factory use.
- (near U6) Reset Threhold 0.84 Volts
- (near R71) NF
- (near R51) NF
- DESIGN NOTE:
  from Design Guide: pullup not required
  JTAG_TDO: no use of external PU/PD
- (near R65) NF
- DESIGN NOTE:
  The proper peripheral RESET (RSTOUTn) should be controlled by processor GPIO, but has to be supported by software first. Temporarily we use the POR to reset peripherals.
- Hardware design courses
- http://www.fedevel.com/academy/
- CONFIDENTAL. Do not distribute.
- Variant:
- Checked by

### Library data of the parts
C83-C86 = C1005C0G1H180J: CAP CER 18PF 50V C0G 5% 0402; Manufacturer: TDK Corporation; .Checked PCB: used; Description: CAP CER 18PF 50V 5% NP0 0402; Temperature Coefficient: C0G, NP0
C87-C89 = C1005X5R1H104K: as C239 on sheet [03] - CONNECTORS
D1 = RB751V-40-TP: DIODE SCHTKY 30MA 30V SOD-323; Manufacturer: Micro Commercial Co; Diode Type: Schottky; Voltage - Forward (Vf) (Max) @ If: 370mV @ 1mA; Speed: Small Signal =< 200mA (Io), Any Speed; Current - Reverse Leakage @ Vr: 500nA @ 30V; Capacitance @ Vr, F: 2pF @ 1V, 1MHz; .Checked PCB: RF
Q9 = 2N7002BKW,115: MOSFET N-CH 60V 310MA SOT323; Manufacturer: NXP Semiconductors; FET Type: MOSFET N-Channel, Metal Oxide; FET Feature: Logic Level Gate; Rds On (Max) @ Id, Vgs: 1.6 Ohm @ 500mA, 10V; Vgs(th) (Max) @ Id: 2.1V @ 250µA; Gate Charge (Qg) @ Vgs: 0.6nC @ 4.5V; Input Capacitance (Ciss) @ Vds: 50pF @ 10V; Power - Max: 275mW; .Checked PCB: RF
R37 = CRCW04022M20FKED: RES 2.20M OHM 1/16W 1% 0402 SMD; Manufacturer: Vishay Dale; Resistance (Ohms): 2.2M; Power (Watts): 0.063W, 1/16W; Temperature Coefficient: ±100ppm/°C; .Creator: MM
R48 R49 R57 R58 R60 R62-R64 R67-R69 R103 R104 R165 = RC0402FR-0710KL: as R38-R43 on sheet [08] - CPU - SPI, I2C, SD, MMC
R51 R65 R70 R71 = RC0402JR-070RL: as R156 on sheet [08] - CPU - SPI, I2C, SD, MMC
R53 R54 = CRCW040210M0FKED: RES 10.0M OHM 1/16W 1% 0402 SMD; Manufacturer: Vishay Dale; Power (Watts): 0.063W, 1/16W; Temperature Coefficient: ±100ppm/°C; .Checked PCB: RF
R55 R56 R59 = RMCF0402FT4K99: as R44 on sheet [08] - CPU - SPI, I2C, SD, MMC
R61 = RC0402FR-071KL: RES 1.00K OHM 1/16W 1% 0402 SMD; Manufacturer: Yageo; Power (Watts): 0.063W, 1/16W; .Checked PCB: used; Temperature Coefficient: ±100ppm/°C
R73 R111 R137 R143 R144 = RMCF0402FT100K: RES 100K OHM 1/16W 1% 0402 SMD; Manufacturer: Stackpole Electronics Inc; Power (Watts): 0.063W, 1/16W; .Checked PCB: used; Temperature Coefficient: ±100ppm/°C
R90 R92 R161 = RC0402FR-0722RL: as R1 on sheet [08] - CPU - SPI, I2C, SD, MMC
TP3 = TP_25MILC: Test Point 25mil
U1 = MCIMX6Q5EYM10AC: as U1 on sheet [08] - CPU - SPI, I2C, SD, MMC
U6 = TPS3808G09DBVR: IC VOLT SUPERVISOR 0.9V SOT23-6; Part #: 102020-0009R; Manufacturer: Texas Instruments; .Checked PCB: used; Number of Voltages Monitored: 1; Output: Open Drain or Open Collector; Reset: Active Low; Reset Timeout: Adjustable/Selectable; Voltage - Threshold: 0.84V
U7 = SN74AHC1G09DBVR: IC GATE AND SGL 2INP SOT23-5; Manufacturer: Texas Instruments; Logic Type: AND Gate; Number of Circuits: 1; Number of Inputs: 2; Voltage - Supply: 2 V ~ 5.5 V; Current - Quiescent (Max): 1µA; Current - Output High, Low: -, 8mA; Logic Level - Low: 0.5 V ~ 1.65 V; Logic Level - High: 1.5 V ~ 3.85 V; Max Propagation Delay @ V, Max CL: 7.5ns @ 5V, 50pF; .Creator: MM; .Checked PCB: RF, used by MM; .Checked SCH: MM, checked by RF
Y1 = ABM7-24.000MHZ-D-2-Y-T: CRYSTAL 24.0000MHZ 18PF SMD; Manufacturer: Abracon Corporation; Frequency Stability: ±30ppm; Frequency Tolerance: ±20ppm; ESR (Equivalent Series Resistance): 50 Ohm; Operating Mode: Fundamental; .Creator: MM; .Checked PCB: RF, used by MM; .Checked SCH: MM, checked by RF
Y2 = ABS06-32.768KHZ-9-1-T: CRYSTAL 32.768 KHZ 9.0 PF SMD; Manufacturer: Abracon Corporation; .Checked PCB: used; Frequency Stability: ±10ppm; Load Capacitance: 9pF; Operating Mode: Fundamental

## Sheet [11] - CPU - POWER.SchDoc
size A2; DocumentNumber: 11; SheetNumber: 11; SheetTotal: 20
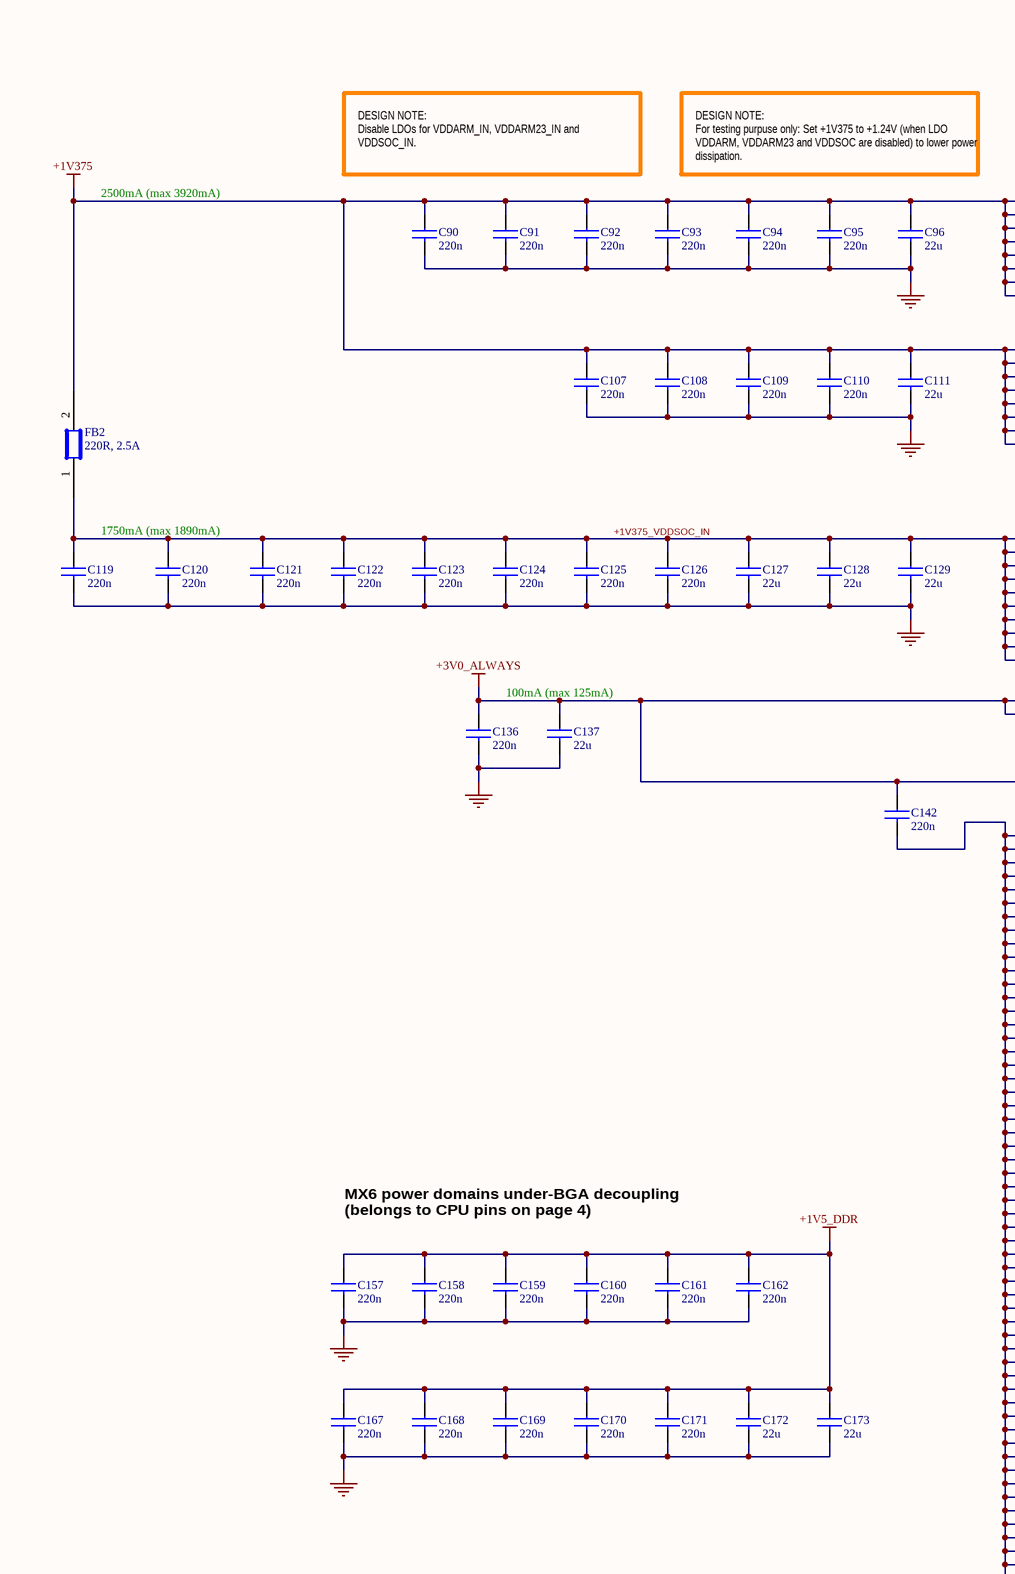
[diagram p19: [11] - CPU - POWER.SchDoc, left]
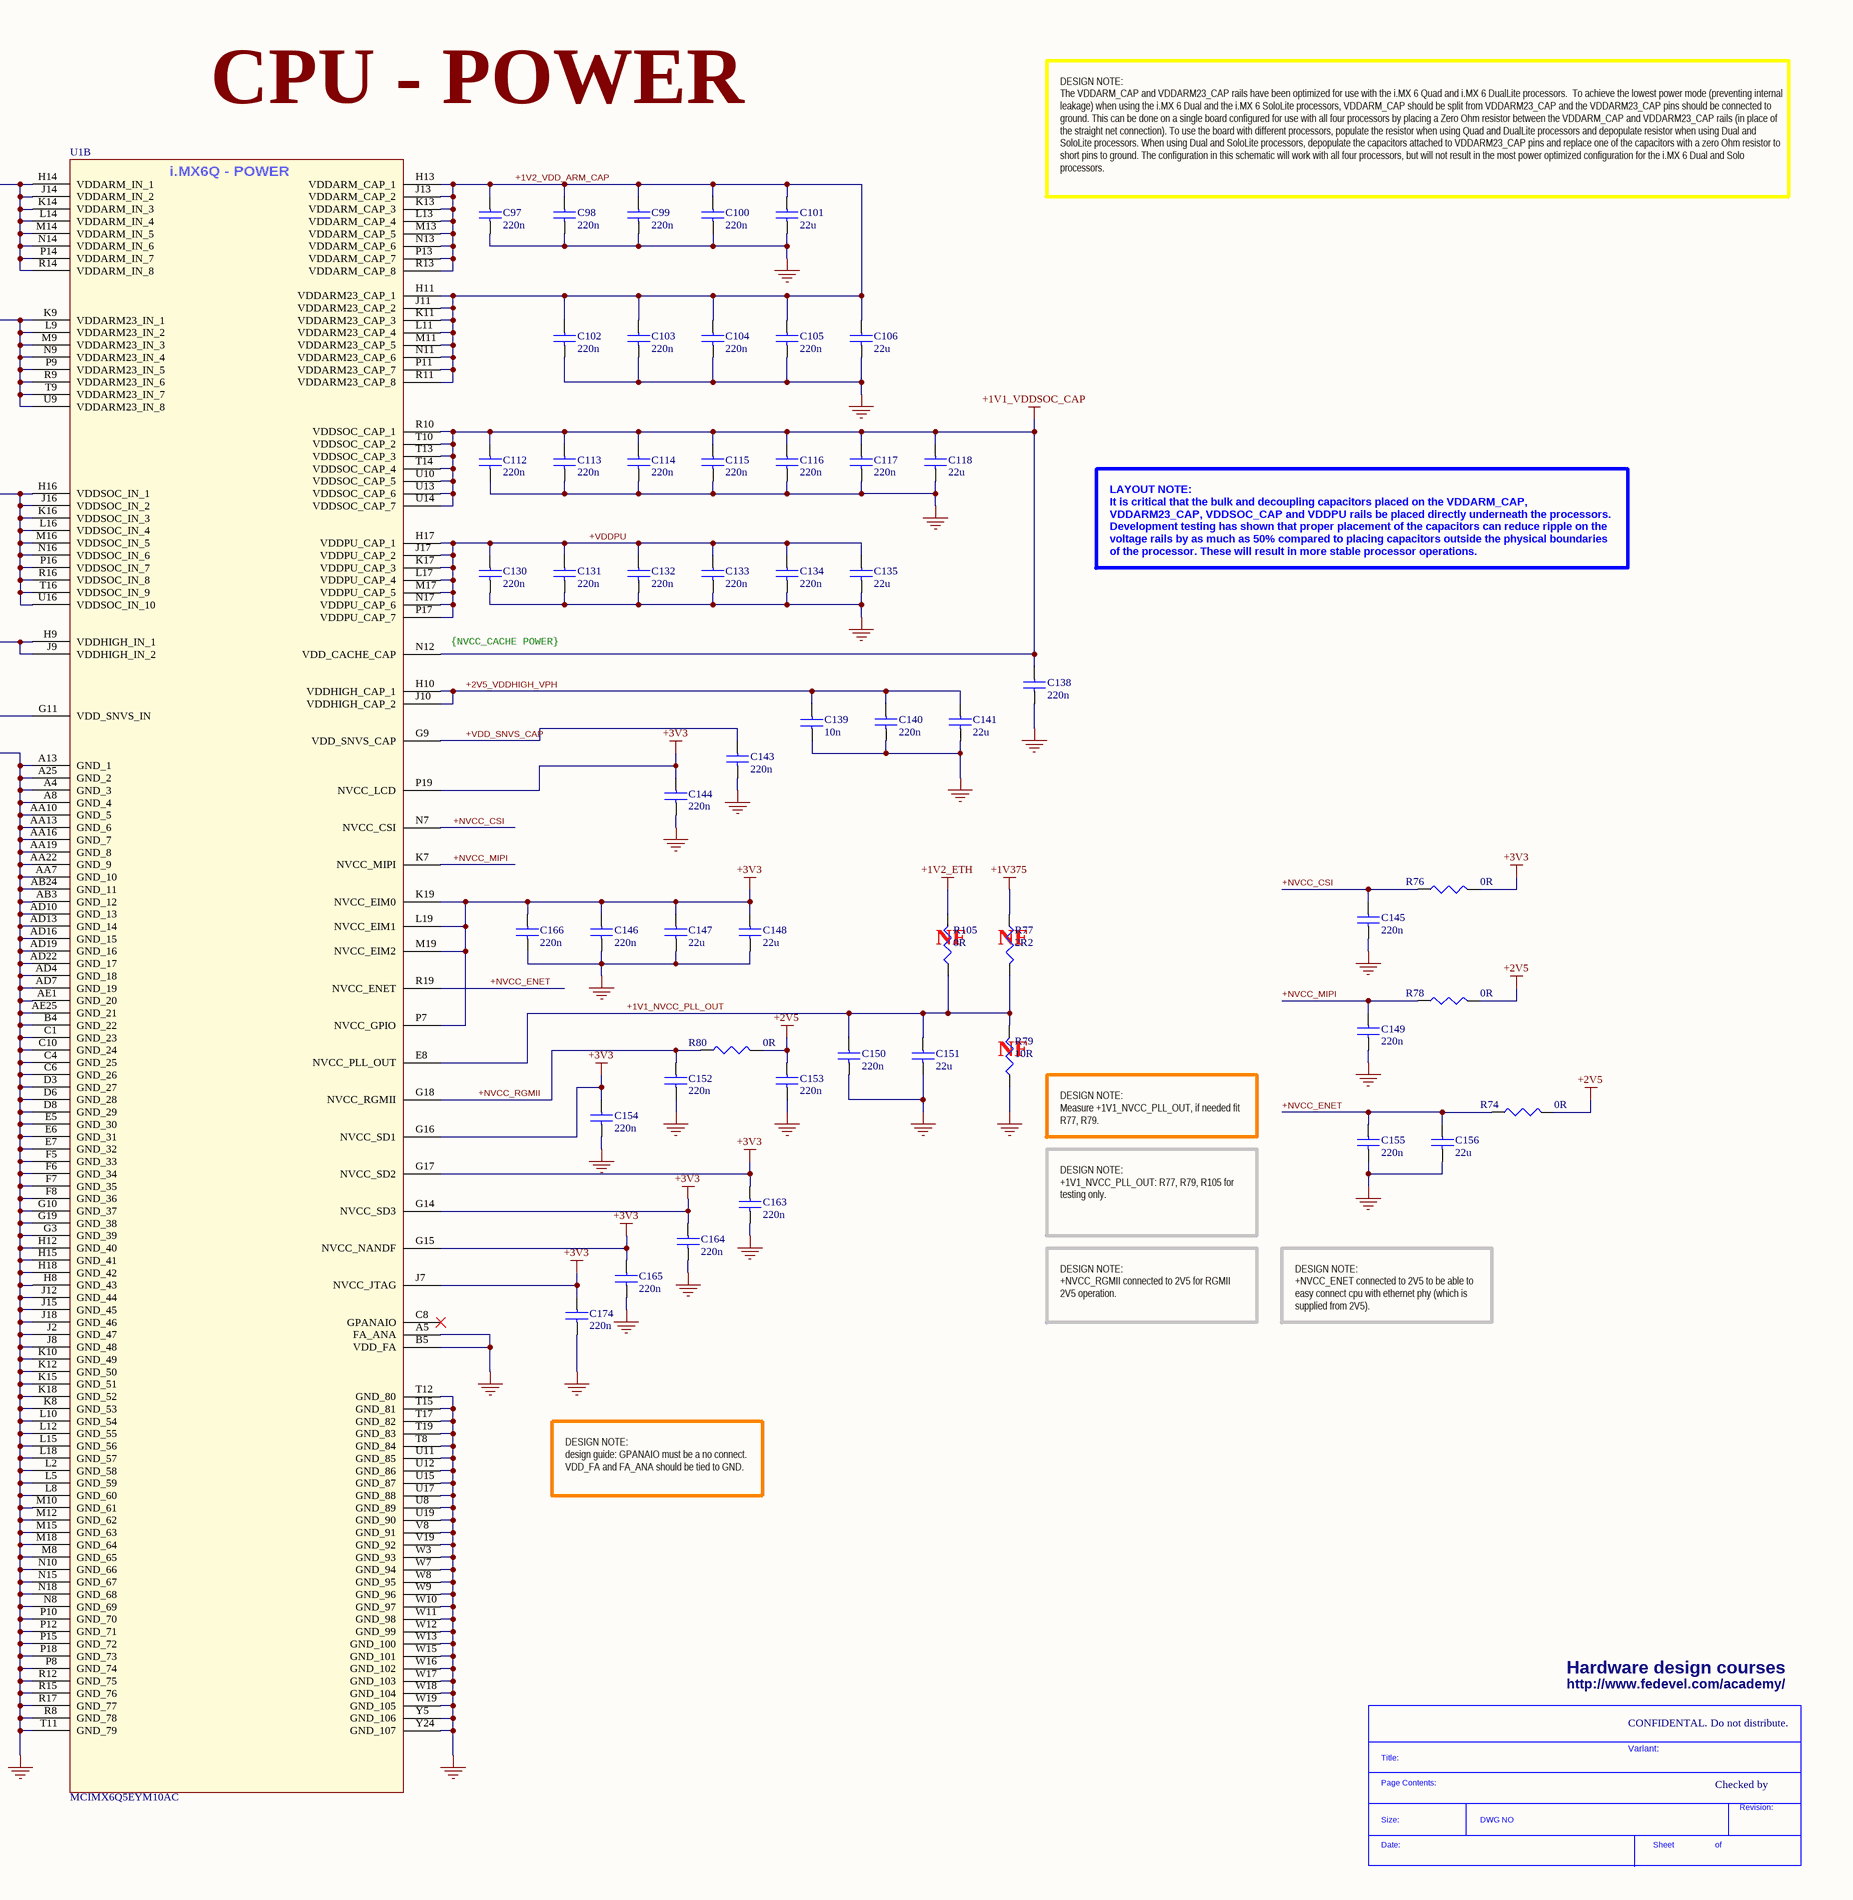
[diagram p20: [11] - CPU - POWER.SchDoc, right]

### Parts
(Parts that share a designator on the sheet are numbered #1, #2 ... from top to bottom, then left to right.)
*#13  SDTitleBlock  (value not drawn)  (graphical)
C90  220n  [C0402]
C91  220n  [C0402]
C92  220n  [C0402]
C93  220n  [C0402]
C94  220n  [C0402]
C95  220n  [C0402]
C96  22u  [C0603]
C97  220n  [C0402]
C98  220n  [C0402]
C99  220n  [C0402]
C100  220n  [C0402]
C101  22u  [C0603]
C102  220n  [C0402]
C103  220n  [C0402]
C104  220n  [C0402]
C105  220n  [C0402]
C106  22u  [C0603]
C107  220n  [C0402]
C108  220n  [C0402]
C109  220n  [C0402]
C110  220n  [C0402]
C111  22u  [C0603]
C112  220n  [C0402]
C113  220n  [C0402]
C114  220n  [C0402]
C115  220n  [C0402]
C116  220n  [C0402]
C117  220n  [C0402]
C118  22u  [C0603]
C119  220n  [C0402]
C120  220n  [C0402]
C121  220n  [C0402]
C122  220n  [C0402]
C123  220n  [C0402]
C124  220n  [C0402]
C125  220n  [C0402]
C126  220n  [C0402]
C127  22u  [C0603]
C128  22u  [C0603]
C129  22u  [C0603]
C130  220n  [C0402]
C131  220n  [C0402]
C132  220n  [C0402]
C133  220n  [C0402]
C134  220n  [C0402]
C135  22u  [C0603]
C136  220n  [C0402]
C137  22u  [C0805]
C138  220n  [C0402]
C139  10n  [C0402]
C140  220n  [C0402]
C141  22u  [C0805]
C142  220n  [C0402]
C143  220n  [C0402]
C144  220n  [C0402]
C145  220n  [C0402]
C146  220n  [C0402]
C147  22u  [C0805]
C148  22u  [C0805]
C149  220n  [C0402]
C150  220n  [C0402]
C151  22u  [C0603]
C152  220n  [C0402]
C153  220n  [C0402]
C154  220n  [C0402]
C155  220n  [C0402]
C156  22u  [C0805]
C157  220n  [C0402]
C158  220n  [C0402]
C159  220n  [C0402]
C160  220n  [C0402]
C161  220n  [C0402]
C162  220n  [C0402]
C163  220n  [C0402]
C164  220n  [C0402]
C165  220n  [C0402]
C166  220n  [C0402]
C167  220n  [C0402]
C168  220n  [C0402]
C169  220n  [C0402]
C170  220n  [C0402]
C171  220n  [C0402]
C172  22u  [C0603]
C173  22u  [C0603]
C174  220n  [C0402]
FB2  220R, 2.5A  [C0603]
R74  0R  [R0402]
R76  0R  [R0402]
R77  2R2  [R0402]
R78  0R  [R0402]
R79  10R  [R0402]
R80  0R  [R0402]
R105  0R  [R0402]
U1  MCIMX6Q5EYM10AC  [PBGA624]  (part B of 15)

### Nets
+1V1_VDDSOC_CAP: C112.1 C113.1 C114.1 C115.1 C116.1 C117.1 C118.1 C138.1 U1.N12(VDD_CACHE_CAP) U1.R10(VDDSOC_CAP_1) U1.T10(VDDSOC_CAP_2) U1.T13(VDDSOC_CAP_3) U1.T14(VDDSOC_CAP_4) U1.U10(VDDSOC_CAP_5) U1.U13(VDDSOC_CAP_6) U1.U14(VDDSOC_CAP_7)
+1V2_ETH: R105.2
+1V5_DDR: C157.1 C158.1 C159.1 C160.1 C161.1 C162.1 C167.1 C168.1 C169.1 C170.1 C171.1 C172.1 C173.1
+1V375: C90.1 C91.1 C92.1 C93.1 C94.1 C95.1 C96.1 C107.1 C108.1 C109.1 C110.1 C111.1 FB2.2 R77.1 U1.H14(VDDARM_IN_1) U1.J14(VDDARM_IN_2) U1.K9(VDDARM23_IN_1) U1.K14(VDDARM_IN_3) U1.L9(VDDARM23_IN_2) U1.L14(VDDARM_IN_4) U1.M9(VDDARM23_IN_3) U1.M14(VDDARM_IN_5) U1.N9(VDDARM23_IN_4) U1.N14(VDDARM_IN_6) U1.P9(VDDARM23_IN_5) U1.P14(VDDARM_IN_7) U1.R9(VDDARM23_IN_6) U1.R14(VDDARM_IN_8) U1.T9(VDDARM23_IN_7) U1.U9(VDDARM23_IN_8)
+2V5: C153.1 R74.2 R78.2 R80.2
+3V0_ALWAYS: C136.1 C137.1 C142.1 U1.G11(VDD_SNVS_IN) U1.H9(VDDHIGH_IN_1) U1.J9(VDDHIGH_IN_2)
+3V3: C144.1 C146.1 C147.1 C148.1 C154.1 C163.1 C164.1 C165.1 C166.1 C174.1 R76.2 U1.G14(NVCC_SD3) U1.G15(NVCC_NANDF) U1.G16(NVCC_SD1) U1.G17(NVCC_SD2) U1.J7(NVCC_JTAG) U1.K19(NVCC_EIM0) U1.L19(NVCC_EIM1) U1.M19(NVCC_EIM2) U1.P7(NVCC_GPIO) U1.P19(NVCC_LCD)
GND: C90.2 C91.2 C92.2 C93.2 C94.2 C95.2 C96.2 C97.2 C98.2 C99.2 C100.2 C101.2 C102.2 C103.2 C104.2 C105.2 C106.2 C107.2 C108.2 C109.2 C110.2 C111.2 C112.2 C113.2 C114.2 C115.2 C116.2 C117.2 C118.2 C119.2 C120.2 C121.2 C122.2 C123.2 C124.2 C125.2 C126.2 C127.2 C128.2 C129.2 C130.2 C131.2 C132.2 C133.2 C134.2 C135.2 C136.2 C137.2 C138.2 C139.1 C140.2 C141.2 C142.2 C143.2 C144.2 C145.2 C146.2 C147.2 C148.2 C149.2 C150.2 C151.2 C152.2 C153.2 C154.2 C155.2 C156.2 C157.2 C158.2 C159.2 C160.2 C161.2 C162.2 C163.2 C164.2 C165.2 C166.2 C167.2 C168.2 C169.2 C170.2 C171.2 C172.2 C173.2 C174.2 R79.1 U1.A4(GND_3) U1.A5(FA_ANA) U1.A8(GND_4) U1.A13(GND_1) U1.A25(GND_2) U1.AA7(GND_10) U1.AA10(GND_5) U1.AA13(GND_6) U1.AA16(GND_7) U1.AA19(GND_8) U1.AA22(GND_9) U1.AB3(GND_12) U1.AB24(GND_11) U1.AD4(GND_18) U1.AD7(GND_19) U1.AD10(GND_13) U1.AD13(GND_14) U1.AD16(GND_15) U1.AD19(GND_16) U1.AD22(GND_17) U1.AE1(GND_20) U1.AE25(GND_21) U1.B4(GND_22) U1.B5(VDD_FA) U1.C1(GND_23) U1.C4(GND_25) U1.C6(GND_26) U1.C10(GND_24) U1.D3(GND_27) U1.D6(GND_28) U1.D8(GND_29) U1.E5(GND_30) U1.E6(GND_31) U1.E7(GND_32) U1.F5(GND_33) U1.F6(GND_34) U1.F7(GND_35) U1.F8(GND_36) U1.G3(GND_39) U1.G10(GND_37) U1.G19(GND_38) U1.H8(GND_43) U1.H12(GND_40) U1.H15(GND_41) U1.H18(GND_42) U1.J2(GND_47) U1.J8(GND_48) U1.J12(GND_44) U1.J15(GND_45) U1.J18(GND_46) U1.K8(GND_53) U1.K10(GND_49) U1.K12(GND_50) U1.K15(GND_51) U1.K18(GND_52) U1.L2(GND_58) U1.L5(GND_59) U1.L8(GND_60) U1.L10(GND_54) U1.L12(GND_55) U1.L15(GND_56) U1.L18(GND_57) U1.M8(GND_65) U1.M10(GND_61) U1.M12(GND_62) U1.M15(GND_63) U1.M18(GND_64) U1.N8(GND_69) U1.N10(GND_66) U1.N15(GND_67) U1.N18(GND_68) U1.P8(GND_74) U1.P10(GND_70) U1.P12(GND_71) U1.P15(GND_72) U1.P18(GND_73) U1.R8(GND_78) U1.R12(GND_75) U1.R15(GND_76) U1.R17(GND_77) U1.T8(GND_84) U1.T11(GND_79) U1.T12(GND_80) U1.T15(GND_81) U1.T17(GND_82) U1.T19(GND_83) U1.U8(GND_89) U1.U11(GND_85) U1.U12(GND_86) U1.U15(GND_87) U1.U17(GND_88) U1.U19(GND_90) U1.V8(GND_91) U1.V19(GND_92) U1.W3(GND_93) U1.W7(GND_94) U1.W8(GND_95) U1.W9(GND_96) U1.W10(GND_97) U1.W11(GND_98) U1.W12(GND_99) U1.W13(GND_100) U1.W15(GND_101) U1.W16(GND_102) U1.W17(GND_103) U1.W18(GND_104) U1.W19(GND_105) U1.Y5(GND_106) U1.Y24(GND_107)
+1V1_NVCC_PLL_OUT: C150.1 C151.1 R77.2 R79.2 R105.1 U1.E8(NVCC_PLL_OUT)
+1V2_VDD_ARM_CAP: C97.1 C98.1 C99.1 C100.1 C101.1 C102.1 C103.1 C104.1 C105.1 C106.1 U1.H11(VDDARM23_CAP_1) U1.H13(VDDARM_CAP_1) U1.J11(VDDARM23_CAP_2) U1.J13(VDDARM_CAP_2) U1.K11(VDDARM23_CAP_3) U1.K13(VDDARM_CAP_3) U1.L11(VDDARM23_CAP_4) U1.L13(VDDARM_CAP_4) U1.M11(VDDARM23_CAP_5) U1.M13(VDDARM_CAP_5) U1.N11(VDDARM23_CAP_6) U1.N13(VDDARM_CAP_6) U1.P11(VDDARM23_CAP_7) U1.P13(VDDARM_CAP_7) U1.R11(VDDARM23_CAP_8) U1.R13(VDDARM_CAP_8)
+1V375_VDDSOC_IN: C119.1 C120.1 C121.1 C122.1 C123.1 C124.1 C125.1 C126.1 C127.1 C128.1 C129.1 FB2.1 U1.H16(VDDSOC_IN_1) U1.J16(VDDSOC_IN_2) U1.K16(VDDSOC_IN_3) U1.L16(VDDSOC_IN_4) U1.M16(VDDSOC_IN_5) U1.N16(VDDSOC_IN_6) U1.P16(VDDSOC_IN_7) U1.R16(VDDSOC_IN_8) U1.T16(VDDSOC_IN_9) U1.U16(VDDSOC_IN_10)
+2V5_VDDHIGH_VPH: C139.2 C140.1 C141.1 U1.H10(VDDHIGH_CAP_1) U1.J10(VDDHIGH_CAP_2)
+NVCC_CSI: C145.1 R76.1 U1.N7(NVCC_CSI)
+NVCC_ENET: C155.1 C156.1 R74.1 U1.R19(NVCC_ENET)
+NVCC_MIPI: C149.1 R78.1 U1.K7(NVCC_MIPI)
+NVCC_RGMII: C152.1 R80.1 U1.G18(NVCC_RGMII)
+VDD_SNVS_CAP: C143.1 U1.G9(VDD_SNVS_CAP)
+VDDPU: C130.1 C131.1 C132.1 C133.1 C134.1 C135.1 U1.H17(VDDPU_CAP_1) U1.J17(VDDPU_CAP_2) U1.K17(VDDPU_CAP_3) U1.L17(VDDPU_CAP_4) U1.M17(VDDPU_CAP_5) U1.N17(VDDPU_CAP_6) U1.P17(VDDPU_CAP_7)

Not connected (* = marked no-connect by the designer): U1 C8(GPANAIO)*

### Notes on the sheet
- CPU - POWER
- 2500mA (max 3920mA)
- DESIGN NOTE:
  Disable LDOs for VDDARM_IN, VDDARM23_IN and VDDSOC_IN.
- DESIGN NOTE:
  For testing purpuse only: Set +1V375 to +1.24V (when LDO VDDARM, VDDARM23 and VDDSOC are disabled) to lower power dissipation.
- DESIGN NOTE:
  The VDDARM_CAP and VDDARM23_CAP rails have been optimized for use with the i.MX 6 Quad and i.MX 6 DualLite processors.  To achieve the lowest power mode (preventing internal leakage) when using the i.MX 6 Dual and the i.MX 6 SoloLite processors, VDDARM_CAP should be split from VDDARM23_CAP and the VDDARM23_CAP pins should be connected to ground. This can be done on a single board configured for use with all four processors by placing a Zero Ohm resistor between the VDDARM_CAP and VDDARM23_CAP rails (in place of the straight net connection). To use the board with different processors, populate the resistor when using Quad and DualLite processors and depopulate resistor when using Dual and SoloLite processors. When using Dual and SoloLite processors, depopulate the capacitors attached to VDDARM23_CAP pins and replace one of the capacitors with a zero Ohm resistor to short pins to ground. The configuration in this schematic will work with all four processors, but will not result in the most power optimized configuration for the i.MX 6 Dual and Solo processors.
- 1750mA (max 1890mA)
- LAYOUT NOTE:
  It is critical that the bulk and decoupling capacitors placed on the VDDARM_CAP, VDDARM23_CAP, VDDSOC_CAP and VDDPU rails be placed directly underneath the processors. Development testing has shown that proper placement of the capacitors can reduce ripple on the voltage rails by as much as 50% compared to placing capacitors outside the physical boundaries of the processor. These will result in more stable processor operations.
- 100mA (max 125mA)
- {NVCC_CACHE POWER}
- (near R105) NF
- (near R77) NF
- (near R79) NF
- MX6 power domains under-BGA decoupling (belongs to CPU pins on page 4)
- DESIGN NOTE:
  Measure +1V1_NVCC_PLL_OUT, if needed fit R77, R79.
- DESIGN NOTE:
  +1V1_NVCC_PLL_OUT: R77, R79, R105 for testing only.
- DESIGN NOTE:
  +NVCC_RGMII connected to 2V5 for RGMII 2V5 operation.
- DESIGN NOTE:
  +NVCC_ENET connected to 2V5 to be able to easy connect cpu with ethernet phy (which is supplied from 2V5).
- DESIGN NOTE:
  design guide: GPANAIO must be a no connect. VDD_FA and FA_ANA should be tied to GND.
- Hardware design courses
- http://www.fedevel.com/academy/
- CONFIDENTAL. Do not distribute.
- Variant:
- Checked by

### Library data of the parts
C90-C95 C97-C100 C102-C105 C107-C110 C112-C117 C119-C126 C130-C134 C136 C138 C140 C142-C146 C149 C150 C152-C155 C157-C171 C174 = C1005X5R1E224M: CAP CER .22UF 25V X5R 20% 0402; Manufacturer: TDK Corporation; Capacitance: 0.22µF; Value: 220nF; .Checked PCB: used; Description: CAP CER 0.22UF 25V 20% X5R 0402
C96 C101 C106 C111 C118 C127-C129 C135 C151 C172 C173 = GRM188R60G226MEA0L: CAP CER 22UF 4V 20% X5R 0603; Manufacturer: Murata Electronics North America; Capacitance: 22µF; .Checked PCB: RF, used by MM; .Checked SCH: MM, checked by RF; .Creator: MM
C137 C141 C147 C148 C156 = C2012X5R1C226K: CAP CER 22UF 16V 10% X5R 0805; Manufacturer: TDK Corporation; Capacitance: 22µF; .Checked PCB: RF
C139 = C1005X7R1H103K: CAP CER 10000PF 50V 10% X7R 0402; Manufacturer: TDK Corporation; Value: 10nF; .Checked PCB: RF
FB2 = BLM18SG221TN1D: FERRITE CHIP 220 OHM 2500MA 0603; Manufacturer: Murata Electronics North America; Impedance @ Frequency: 220 Ohm @ 100MHz; DC Resistance (DCR): 40 mOhm Max; Filter Type: Differential Mode - Single; Number of Lines: 1; .Checked PCB: RF
R74 R76 R78 R80 R105 = RC0402JR-070RL: as R156 on sheet [08] - CPU - SPI, I2C, SD, MMC
R77 = CRCW04022R20FKED: RES 2.20 OHM 1/16W 1% 0402 SMD; Manufacturer: Vishay Dale; Resistance (Ohms): 2.2; Power (Watts): 0.063W, 1/16W; Temperature Coefficient: ±100ppm/°C; .Checked PCB: RF
R79 = RC0402FR-0710RL: RES 10.0 OHM 1/16W 1% 0402 SMD; Manufacturer: Yageo; Resistance (Ohms): 10; Power (Watts): 0.063W, 1/16W; .Checked PCB: used; Temperature Coefficient: ±200ppm/°C
U1 = MCIMX6Q5EYM10AC: as U1 on sheet [08] - CPU - SPI, I2C, SD, MMC

## Sheet [12] - CPU - UNUSED.SchDoc
size A2; DocumentNumber: 12; SheetNumber: 12; SheetTotal: 20
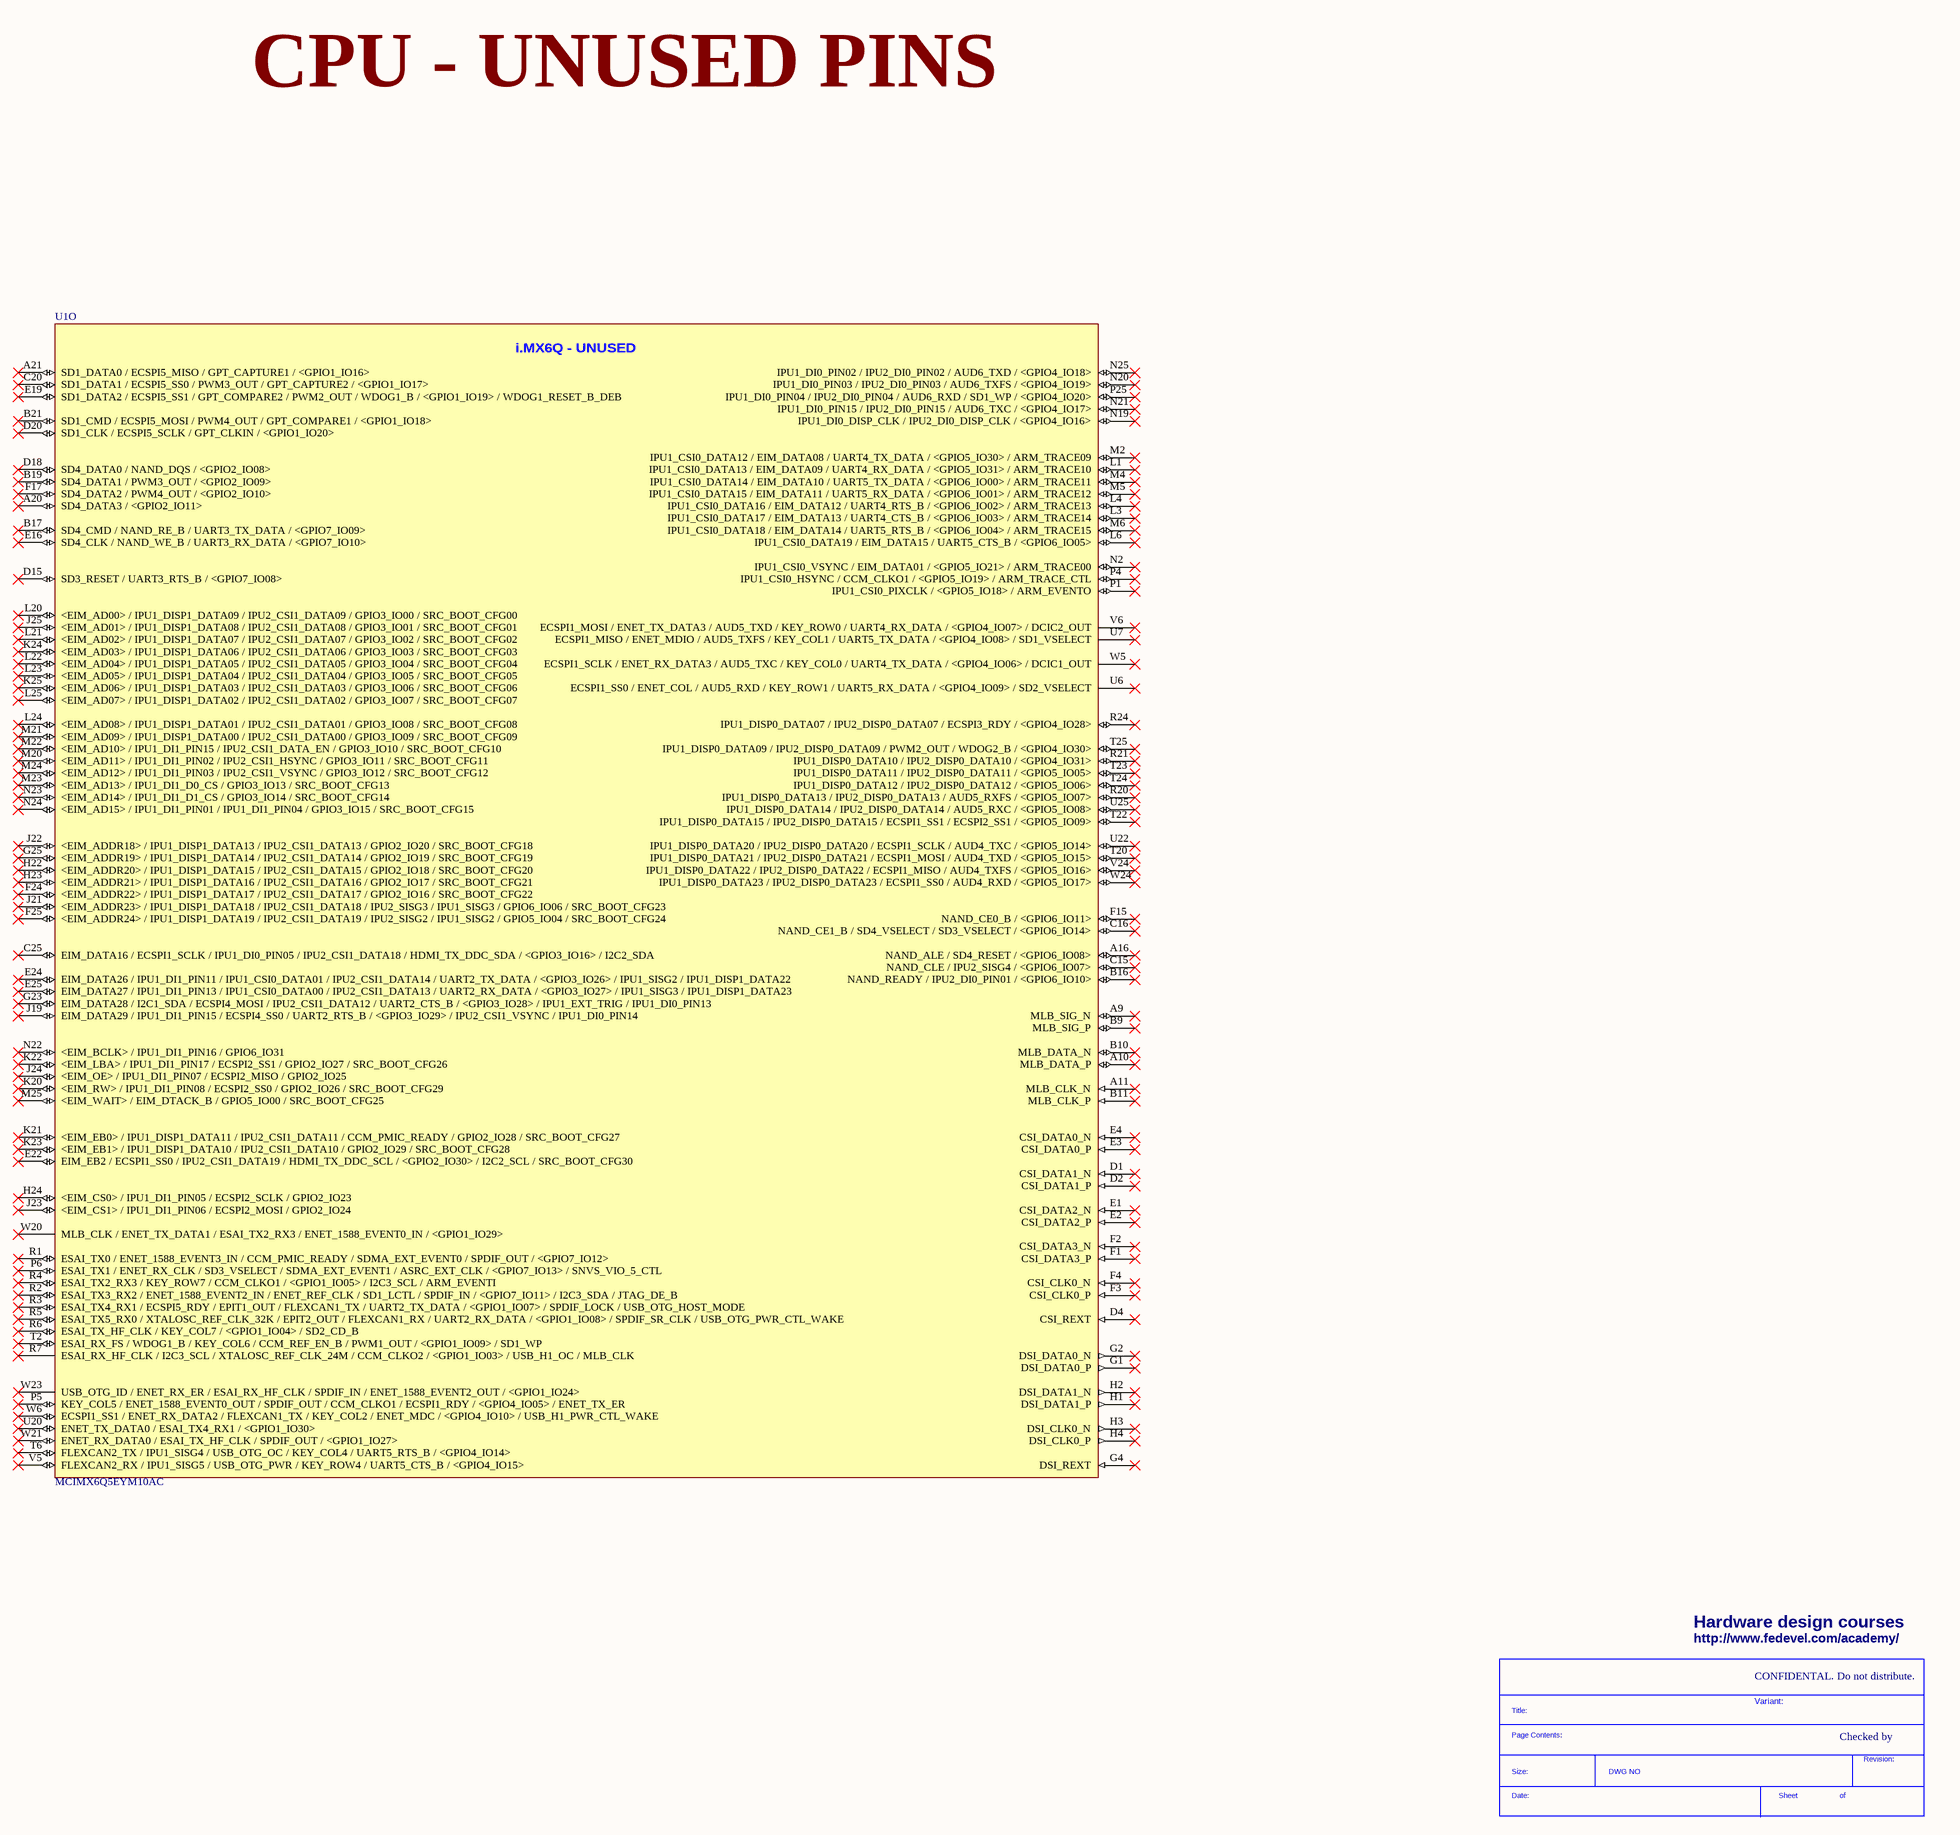
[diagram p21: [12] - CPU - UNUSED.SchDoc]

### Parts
(Parts that share a designator on the sheet are numbered #1, #2 ... from top to bottom, then left to right.)
*#14  SDTitleBlock  (value not drawn)  (graphical)
U1  MCIMX6Q5EYM10AC  [PBGA624]  (part O of 15)

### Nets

Not connected (* = marked no-connect by the designer): U1 A9(MLB_SIG_N)* A10(MLB_DATA_P)* A11(MLB_CLK_N)* A16(NAND_ALE_/_SD4_RESET_/_<GPIO6_IO08>)* A20(SD4_DATA3_/_<GPIO2_IO11>)* A21(SD1_DATA0_/_ECSPI5_MISO_/_GPT_CAPTURE1_/_<GPIO1_IO16>)* B9(MLB_SIG_P)* B10(MLB_DATA_N)* B11(MLB_CLK_P)* B16(NAND_READY_/_IPU2_DI0_PIN01_/_<GPIO6_IO10>)* B17(SD4_CMD_/_NAND_RE_B_/_UART3_TX_DATA_/_<GPIO7_IO09>)* B19(SD4_DATA1_/_PWM3_OUT_/_<GPIO2_IO09>)* B21(SD1_CMD_/_ECSPI5_MOSI_/_PWM4_OUT_/_GPT_COMPARE1_/_<GPIO1_IO18>)* C15(NAND_CLE_/_IPU2_SISG4_/_<GPIO6_IO07>)* C16(NAND_CE1_B_/_SD4_VSELECT_/_SD3_VSELECT_/_<GPIO6_IO14>)* C20(SD1_DATA1_/_ECSPI5_SS0_/_PWM3_OUT_/_GPT_CAPTURE2_/_<GPIO1_IO17>)* C25(EIM_DATA16_/_ECSPI1_SCLK_/_IPU1_DI0_PIN05_/_IPU2_CSI1_DATA18_/_HDMI_TX_DDC_SDA_/_<GPIO3_IO16>_/_I2C2_SDA)* D1(CSI_DATA1_N)* D2(CSI_DATA1_P)* D4(CSI_REXT)* D15(SD3_RESET_/_UART3_RTS_B_/_<GPIO7_IO08>)* D18(SD4_DATA0_/_NAND_DQS_/_<GPIO2_IO08>)* D20(SD1_CLK_/_ECSPI5_SCLK_/_GPT_CLKIN_/_<GPIO1_IO20>)* E1(CSI_DATA2_N)* E2(CSI_DATA2_P)* E3(CSI_DATA0_P)* E4(CSI_DATA0_N)* E16(SD4_CLK_/_NAND_WE_B_/_UART3_RX_DATA_/_<GPIO7_IO10>)* E19(SD1_DATA2_/_ECSPI5_SS1_/_GPT_COMPARE2_/_PWM2_OUT_/_WDOG1_B_/_<GPIO1_IO19>_/_WDOG1_RESET_B_DEB)* E22(EIM_EB2_/_ECSPI1_SS0_/_IPU2_CSI1_DATA19_/_HDMI_TX_DDC_SCL_/_<GPIO2_IO30>_/_I2C2_SCL_/_SRC_BOOT_CFG30)* E24(EIM_DATA26_/_IPU1_DI1_PIN11_/_IPU1_CSI0_DATA01_/_IPU2_CSI1_DATA14_/_UART2_TX_DATA_/_<GPIO3_IO26>_/_IPU1_SISG2_/_IPU1_DISP1_DATA22)* E25(EIM_DATA27_/_IPU1_DI1_PIN13_/_IPU1_CSI0_DATA00_/_IPU2_CSI1_DATA13_/_UART2_RX_DATA_/_<GPIO3_IO27>_/_IPU1_SISG3_/_IPU1_DISP1_DATA23)* F1(CSI_DATA3_P)* F2(CSI_DATA3_N)* F3(CSI_CLK0_P)* F4(CSI_CLK0_N)* F15(NAND_CE0_B_/_<GPIO6_IO11>)* F17(SD4_DATA2_/_PWM4_OUT_/_<GPIO2_IO10>)* F24(<EIM_ADDR22>_/_IPU1_DISP1_DATA17_/_IPU2_CSI1_DATA17_/_GPIO2_IO16_/_SRC_BOOT_CFG22)* F25(<EIM_ADDR24>_/_IPU1_DISP1_DATA19_/_IPU2_CSI1_DATA19_/_IPU2_SISG2_/_IPU1_SISG2_/_GPIO5_IO04_/_SRC_BOOT_CFG24)* G1(DSI_DATA0_P)* G2(DSI_DATA0_N)* G4(DSI_REXT)* G23(EIM_DATA28_/_I2C1_SDA_/_ECSPI4_MOSI_/_IPU2_CSI1_DATA12_/_UART2_CTS_B_/_<GPIO3_IO28>_/_IPU1_EXT_TRIG_/_IPU1_DI0_PIN13)* G25(<EIM_ADDR19>_/_IPU1_DISP1_DATA14_/_IPU2_CSI1_DATA14_/_GPIO2_IO19_/_SRC_BOOT_CFG19)* H1(DSI_DATA1_P)* H2(DSI_DATA1_N)* H3(DSI_CLK0_N)* H4(DSI_CLK0_P)* H22(<EIM_ADDR20>_/_IPU1_DISP1_DATA15_/_IPU2_CSI1_DATA15_/_GPIO2_IO18_/_SRC_BOOT_CFG20)* H23(<EIM_ADDR21>_/_IPU1_DISP1_DATA16_/_IPU2_CSI1_DATA16_/_GPIO2_IO17_/_SRC_BOOT_CFG21)* H24(<EIM_CS0>_/_IPU1_DI1_PIN05_/_ECSPI2_SCLK_/_GPIO2_IO23)* J19(EIM_DATA29_/_IPU1_DI1_PIN15_/_ECSPI4_SS0_/_UART2_RTS_B_/_<GPIO3_IO29>_/_IPU2_CSI1_VSYNC_/_IPU1_DI0_PIN14)* J21(<EIM_ADDR23>_/_IPU1_DISP1_DATA18_/_IPU2_CSI1_DATA18_/_IPU2_SISG3_/_IPU1_SISG3_/_GPIO6_IO06_/_SRC_BOOT_CFG23)* J22(<EIM_ADDR18>_/_IPU1_DISP1_DATA13_/_IPU2_CSI1_DATA13_/_GPIO2_IO20_/_SRC_BOOT_CFG18)* J23(<EIM_CS1>_/_IPU1_DI1_PIN06_/_ECSPI2_MOSI_/_GPIO2_IO24)* J24(<EIM_OE>_/_IPU1_DI1_PIN07_/_ECSPI2_MISO_/_GPIO2_IO25)* J25(<EIM_AD01>_/_IPU1_DISP1_DATA08_/_IPU2_CSI1_DATA08_/_GPIO3_IO01_/_SRC_BOOT_CFG01)* K20(<EIM_RW>_/_IPU1_DI1_PIN08_/_ECSPI2_SS0_/_GPIO2_IO26_/_SRC_BOOT_CFG29)* K21(<EIM_EB0>_/_IPU1_DISP1_DATA11_/_IPU2_CSI1_DATA11_/_CCM_PMIC_READY_/_GPIO2_IO28_/_SRC_BOOT_CFG27)* K22(<EIM_LBA>_/_IPU1_DI1_PIN17_/_ECSPI2_SS1_/_GPIO2_IO27_/_SRC_BOOT_CFG26)* K23(<EIM_EB1>_/_IPU1_DISP1_DATA10_/_IPU2_CSI1_DATA10_/_GPIO2_IO29_/_SRC_BOOT_CFG28)* K24(<EIM_AD03>_/_IPU1_DISP1_DATA06_/_IPU2_CSI1_DATA06_/_GPIO3_IO03_/_SRC_BOOT_CFG03)* K25(<EIM_AD06>_/_IPU1_DISP1_DATA03_/_IPU2_CSI1_DATA03_/_GPIO3_IO06_/_SRC_BOOT_CFG06)* L1(IPU1_CSI0_DATA13_/_EIM_DATA09_/_UART4_RX_DATA_/_<GPIO5_IO31>_/_ARM_TRACE10)* L3(IPU1_CSI0_DATA17_/_EIM_DATA13_/_UART4_CTS_B_/_<GPIO6_IO03>_/_ARM_TRACE14)* L4(IPU1_CSI0_DATA16_/_EIM_DATA12_/_UART4_RTS_B_/_<GPIO6_IO02>_/_ARM_TRACE13)* L6(IPU1_CSI0_DATA19_/_EIM_DATA15_/_UART5_CTS_B_/_<GPIO6_IO05>)* L20(<EIM_AD00>_/_IPU1_DISP1_DATA09_/_IPU2_CSI1_DATA09_/_GPIO3_IO00_/_SRC_BOOT_CFG00)* L21(<EIM_AD02>_/_IPU1_DISP1_DATA07_/_IPU2_CSI1_DATA07_/_GPIO3_IO02_/_SRC_BOOT_CFG02)* L22(<EIM_AD04>_/_IPU1_DISP1_DATA05_/_IPU2_CSI1_DATA05_/_GPIO3_IO04_/_SRC_BOOT_CFG04)* L23(<EIM_AD05>_/_IPU1_DISP1_DATA04_/_IPU2_CSI1_DATA04_/_GPIO3_IO05_/_SRC_BOOT_CFG05)* L24(<EIM_AD08>_/_IPU1_DISP1_DATA01_/_IPU2_CSI1_DATA01_/_GPIO3_IO08_/_SRC_BOOT_CFG08)* L25(<EIM_AD07>_/_IPU1_DISP1_DATA02_/_IPU2_CSI1_DATA02_/_GPIO3_IO07_/_SRC_BOOT_CFG07)* M2(IPU1_CSI0_DATA12_/_EIM_DATA08_/_UART4_TX_DATA_/_<GPIO5_IO30>_/_ARM_TRACE09)* M4(IPU1_CSI0_DATA14_/_EIM_DATA10_/_UART5_TX_DATA_/_<GPIO6_IO00>_/_ARM_TRACE11)* M5(IPU1_CSI0_DATA15_/_EIM_DATA11_/_UART5_RX_DATA_/_<GPIO6_IO01>_/_ARM_TRACE12)* M6(IPU1_CSI0_DATA18_/_EIM_DATA14_/_UART5_RTS_B_/_<GPIO6_IO04>_/_ARM_TRACE15)* M20(<EIM_AD11>_/_IPU1_DI1_PIN02_/_IPU2_CSI1_HSYNC_/_GPIO3_IO11_/_SRC_BOOT_CFG11)* M21(<EIM_AD09>_/_IPU1_DISP1_DATA00_/_IPU2_CSI1_DATA00_/_GPIO3_IO09_/_SRC_BOOT_CFG09)* M22(<EIM_AD10>_/_IPU1_DI1_PIN15_/_IPU2_CSI1_DATA_EN_/_GPIO3_IO10_/_SRC_BOOT_CFG10)* M23(<EIM_AD13>_/_IPU1_DI1_D0_CS_/_GPIO3_IO13_/_SRC_BOOT_CFG13)* M24(<EIM_AD12>_/_IPU1_DI1_PIN03_/_IPU2_CSI1_VSYNC_/_GPIO3_IO12_/_SRC_BOOT_CFG12)* M25(<EIM_WAIT>_/_EIM_DTACK_B_/_GPIO5_IO00_/_SRC_BOOT_CFG25)* N2(IPU1_CSI0_VSYNC_/_EIM_DATA01_/_<GPIO5_IO21>_/_ARM_TRACE00)* N19(IPU1_DI0_DISP_CLK_/_IPU2_DI0_DISP_CLK_/_<GPIO4_IO16>)* N20(IPU1_DI0_PIN03_/_IPU2_DI0_PIN03_/_AUD6_TXFS_/_<GPIO4_IO19>)* N21(IPU1_DI0_PIN15_/_IPU2_DI0_PIN15_/_AUD6_TXC_/_<GPIO4_IO17>)* N22(<EIM_BCLK>_/_IPU1_DI1_PIN16_/_GPIO6_IO31)* N23(<EIM_AD14>_/_IPU1_DI1_D1_CS_/_GPIO3_IO14_/_SRC_BOOT_CFG14)* N24(<EIM_AD15>_/_IPU1_DI1_PIN01_/_IPU1_DI1_PIN04_/_GPIO3_IO15_/_SRC_BOOT_CFG15)* N25(IPU1_DI0_PIN02_/_IPU2_DI0_PIN02_/_AUD6_TXD_/_<GPIO4_IO18>)* P1(IPU1_CSI0_PIXCLK_/_<GPIO5_IO18>_/_ARM_EVENTO)* P4(IPU1_CSI0_HSYNC_/_CCM_CLKO1_/_<GPIO5_IO19>_/_ARM_TRACE_CTL)* P5(KEY_COL5_/_ENET_1588_EVENT0_OUT_/_SPDIF_OUT_/_CCM_CLKO1_/_ECSPI1_RDY_/_<GPIO4_IO05>_/_ENET_TX_ER)* P6(ESAI_TX1_/_ENET_RX_CLK_/_SD3_VSELECT_/_SDMA_EXT_EVENT1_/_ASRC_EXT_CLK_/_<GPIO7_IO13>_/_SNVS_VIO_5_CTL)* P25(IPU1_DI0_PIN04_/_IPU2_DI0_PIN04_/_AUD6_RXD_/_SD1_WP_/_<GPIO4_IO20>)* R1(ESAI_TX0_/_ENET_1588_EVENT3_IN_/_CCM_PMIC_READY_/_SDMA_EXT_EVENT0_/_SPDIF_OUT_/_<GPIO7_IO12>)* R2(ESAI_TX3_RX2_/_ENET_1588_EVENT2_IN_/_ENET_REF_CLK_/_SD1_LCTL_/_SPDIF_IN_/_<GPIO7_IO11>_/_I2C3_SDA_/_JTAG_DE_B)* R3(ESAI_TX4_RX1_/_ECSPI5_RDY_/_EPIT1_OUT_/_FLEXCAN1_TX_/_UART2_TX_DATA_/_<GPIO1_IO07>_/_SPDIF_LOCK_/_USB_OTG_HOST_MODE)* R4(ESAI_TX2_RX3_/_KEY_ROW7_/_CCM_CLKO1_/_<GPIO1_IO05>_/_I2C3_SCL_/_ARM_EVENTI)* R5(ESAI_TX5_RX0_/_XTALOSC_REF_CLK_32K_/_EPIT2_OUT_/_FLEXCAN1_RX_/_UART2_RX_DATA_/_<GPIO1_IO08>_/_SPDIF_SR_CLK_/_USB_OTG_PWR_CTL_WAKE)* R6(ESAI_TX_HF_CLK_/_KEY_COL7_/_<GPIO1_IO04>_/_SD2_CD_B)* R7(ESAI_RX_HF_CLK_/_I2C3_SCL_/_XTALOSC_REF_CLK_24M_/_CCM_CLKO2_/_<GPIO1_IO03>_/_USB_H1_OC_/_MLB_CLK)* R20(IPU1_DISP0_DATA13_/_IPU2_DISP0_DATA13_/_AUD5_RXFS_/_<GPIO5_IO07>)* R21(IPU1_DISP0_DATA10_/_IPU2_DISP0_DATA10_/_<GPIO4_IO31>)* R24(IPU1_DISP0_DATA07_/_IPU2_DISP0_DATA07_/_ECSPI3_RDY_/_<GPIO4_IO28>)* T2(ESAI_RX_FS_/_WDOG1_B_/_KEY_COL6_/_CCM_REF_EN_B_/_PWM1_OUT_/_<GPIO1_IO09>_/_SD1_WP)* T6(FLEXCAN2_TX_/_IPU1_SISG4_/_USB_OTG_OC_/_KEY_COL4_/_UART5_RTS_B_/_<GPIO4_IO14>)* T20(IPU1_DISP0_DATA21_/_IPU2_DISP0_DATA21_/_ECSPI1_MOSI_/_AUD4_TXD_/_<GPIO5_IO15>)* T22(IPU1_DISP0_DATA15_/_IPU2_DISP0_DATA15_/_ECSPI1_SS1_/_ECSPI2_SS1_/_<GPIO5_IO09>)* T23(IPU1_DISP0_DATA11_/_IPU2_DISP0_DATA11_/_<GPIO5_IO05>)* T24(IPU1_DISP0_DATA12_/_IPU2_DISP0_DATA12_/_<GPIO5_IO06>)* T25(IPU1_DISP0_DATA09_/_IPU2_DISP0_DATA09_/_PWM2_OUT_/_WDOG2_B_/_<GPIO4_IO30>)* U6(ECSPI1_SS0_/_ENET_COL_/_AUD5_RXD_/_KEY_ROW1_/_UART5_RX_DATA_/_<GPIO4_IO09>_/_SD2_VSELECT)* U7(ECSPI1_MISO_/_ENET_MDIO_/_AUD5_TXFS_/_KEY_COL1_/_UART5_TX_DATA_/_<GPIO4_IO08>_/_SD1_VSELECT)* U20(ENET_TX_DATA0_/_ESAI_TX4_RX1_/_<GPIO1_IO30>)* U22(IPU1_DISP0_DATA20_/_IPU2_DISP0_DATA20_/_ECSPI1_SCLK_/_AUD4_TXC_/_<GPIO5_IO14>)* U25(IPU1_DISP0_DATA14_/_IPU2_DISP0_DATA14_/_AUD5_RXC_/_<GPIO5_IO08>)* V5(FLEXCAN2_RX_/_IPU1_SISG5_/_USB_OTG_PWR_/_KEY_ROW4_/_UART5_CTS_B_/_<GPIO4_IO15>)* V6(ECSPI1_MOSI_/_ENET_TX_DATA3_/_AUD5_TXD_/_KEY_ROW0_/_UART4_RX_DATA_/_<GPIO4_IO07>_/_DCIC2_OUT)* V24(IPU1_DISP0_DATA22_/_IPU2_DISP0_DATA22_/_ECSPI1_MISO_/_AUD4_TXFS_/_<GPIO5_IO16>)* W5(ECSPI1_SCLK_/_ENET_RX_DATA3_/_AUD5_TXC_/_KEY_COL0_/_UART4_TX_DATA_/_<GPIO4_IO06>_/_DCIC1_OUT)* W6(ECSPI1_SS1_/_ENET_RX_DATA2_/_FLEXCAN1_TX_/_KEY_COL2_/_ENET_MDC_/_<GPIO4_IO10>_/_USB_H1_PWR_CTL_WAKE)* W20(MLB_CLK_/_ENET_TX_DATA1_/_ESAI_TX2_RX3_/_ENET_1588_EVENT0_IN_/_<GPIO1_IO29>)* W21(ENET_RX_DATA0_/_ESAI_TX_HF_CLK_/_SPDIF_OUT_/_<GPIO1_IO27>)* W23(USB_OTG_ID_/_ENET_RX_ER_/_ESAI_RX_HF_CLK_/_SPDIF_IN_/_ENET_1588_EVENT2_OUT_/_<GPIO1_IO24>)* W24(IPU1_DISP0_DATA23_/_IPU2_DISP0_DATA23_/_ECSPI1_SS0_/_AUD4_RXD_/_<GPIO5_IO17>)*

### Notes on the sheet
- CPU - UNUSED PINS
- Hardware design courses
- http://www.fedevel.com/academy/
- CONFIDENTAL. Do not distribute.
- Variant:
- Checked by

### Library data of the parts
U1 = MCIMX6Q5EYM10AC: as U1 on sheet [08] - CPU - SPI, I2C, SD, MMC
